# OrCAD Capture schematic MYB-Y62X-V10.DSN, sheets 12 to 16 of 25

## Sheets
12 PAGE10 - DUAL CHANNELS LVDS #: size A3; note: LVD1S & LVDS2
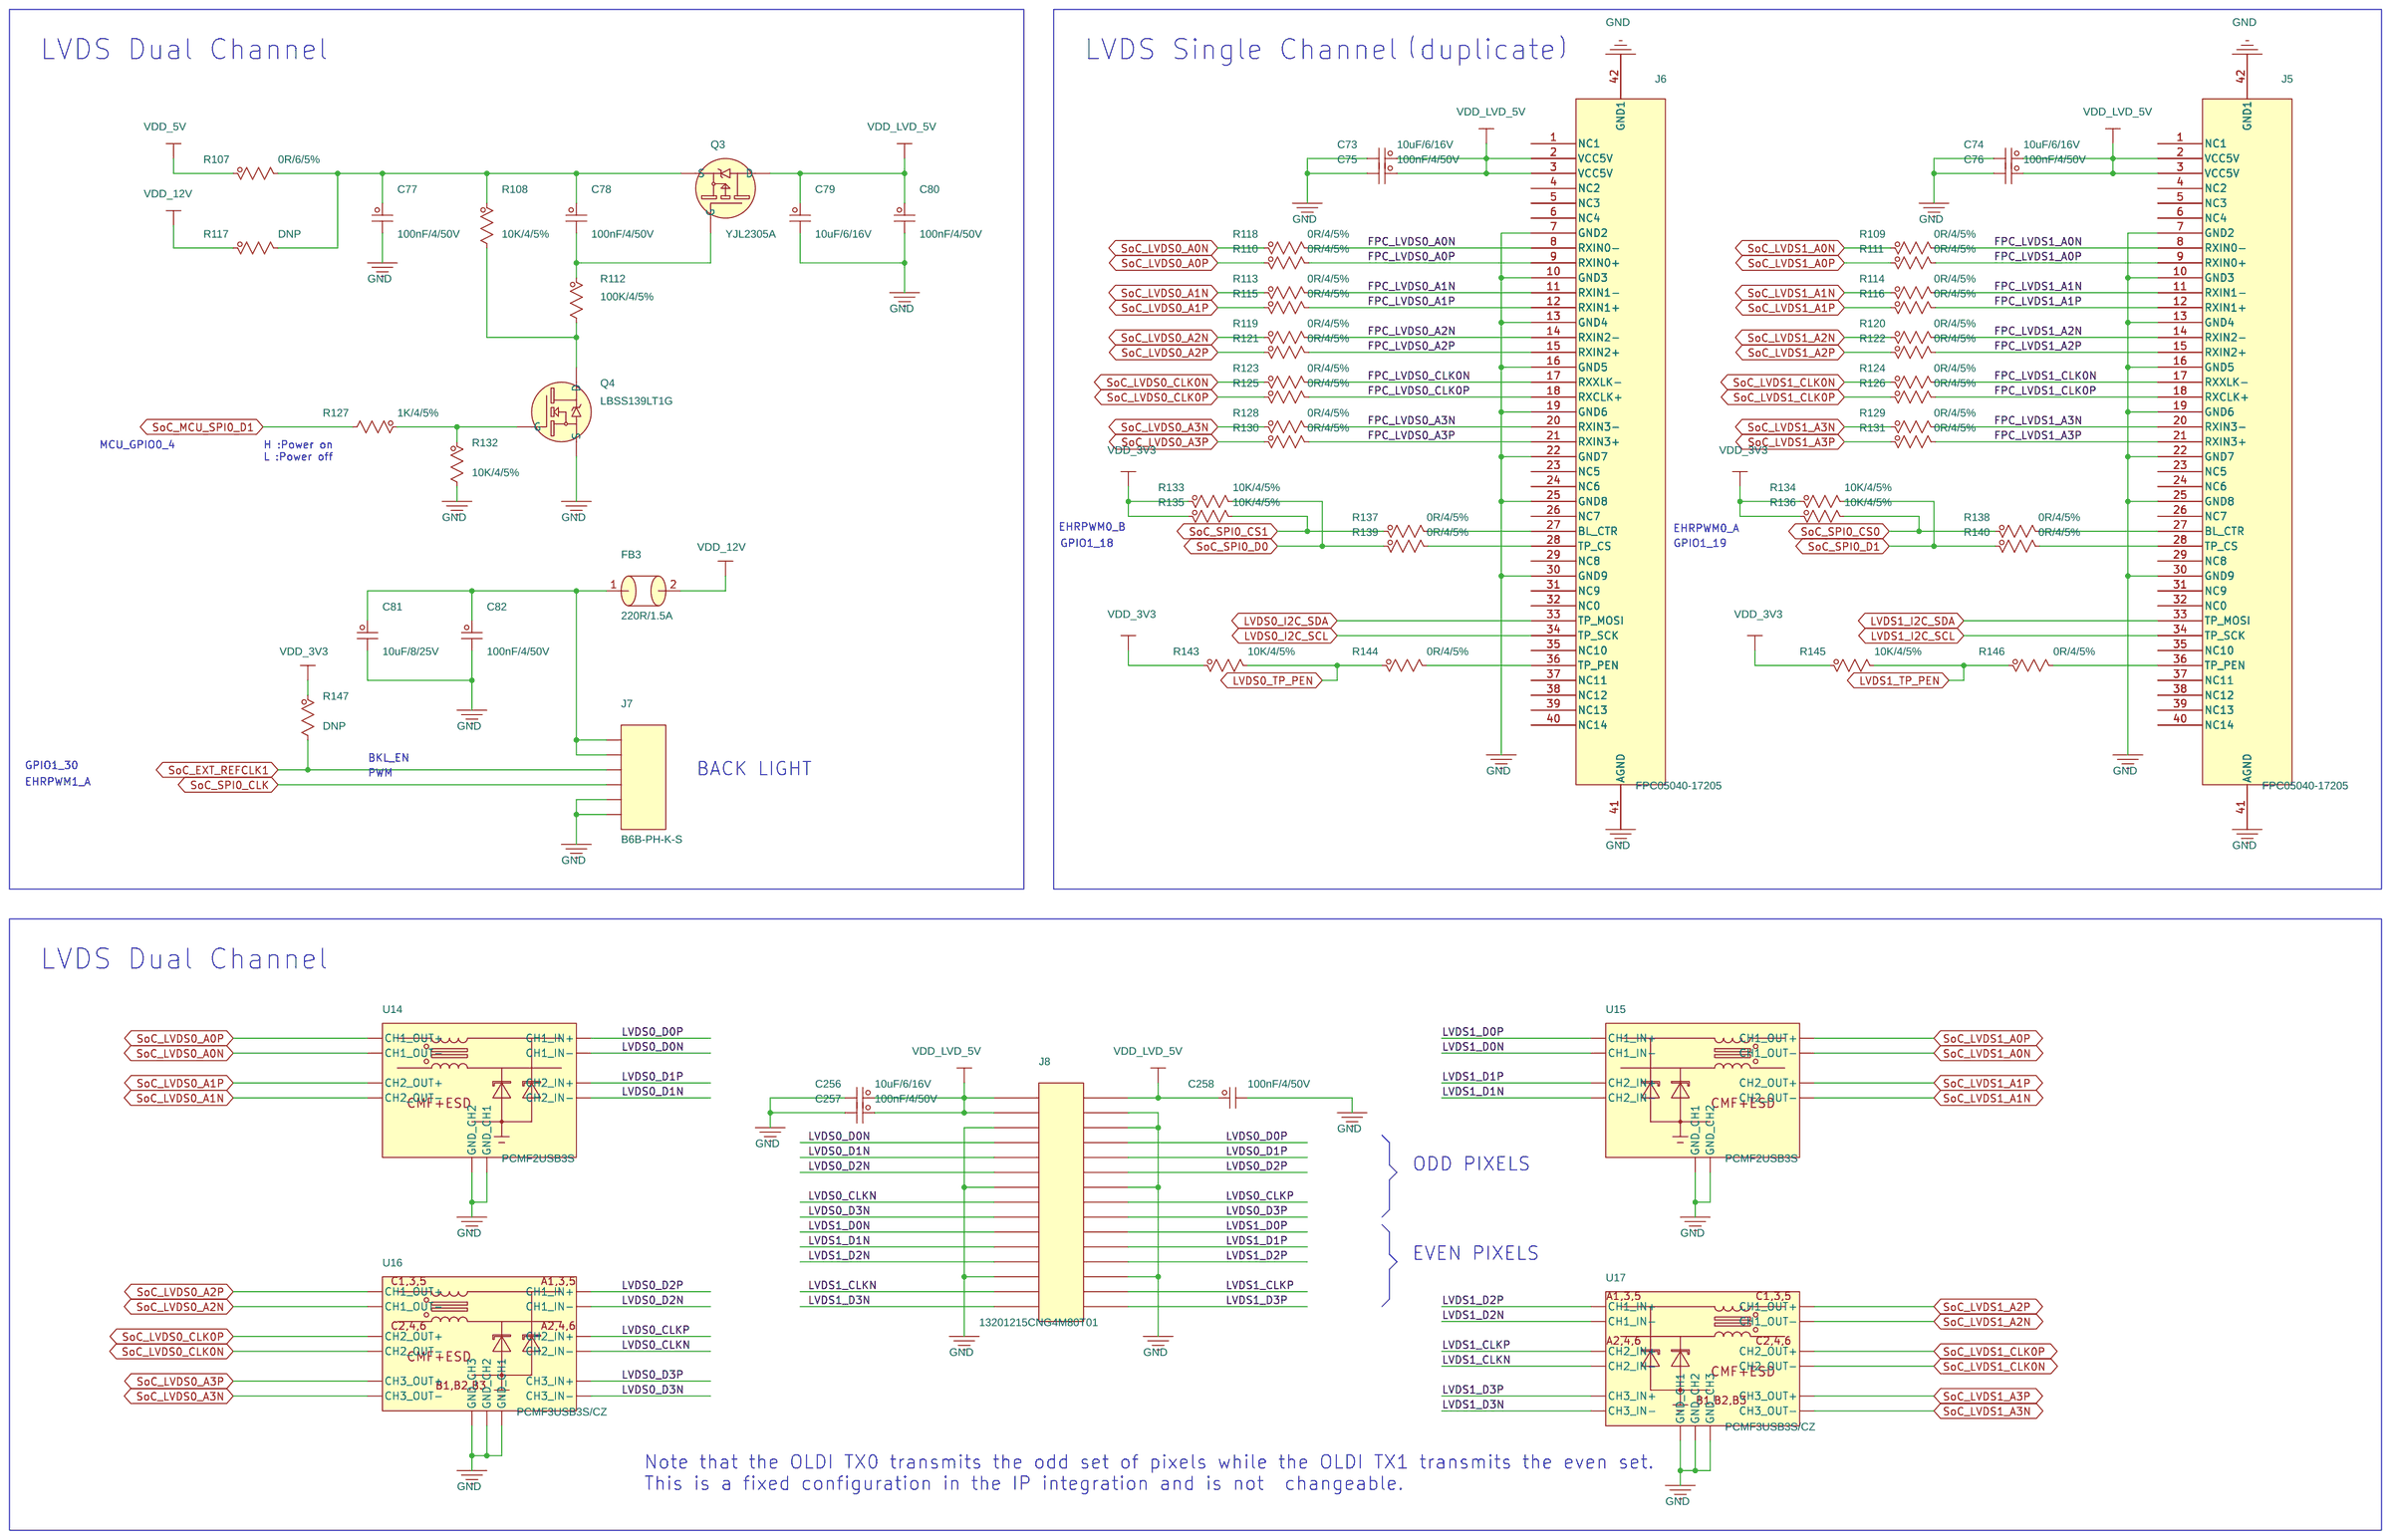
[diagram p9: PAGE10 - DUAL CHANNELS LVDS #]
13 PAGE11 - CSI - RX: size A3; note: CSI - RX
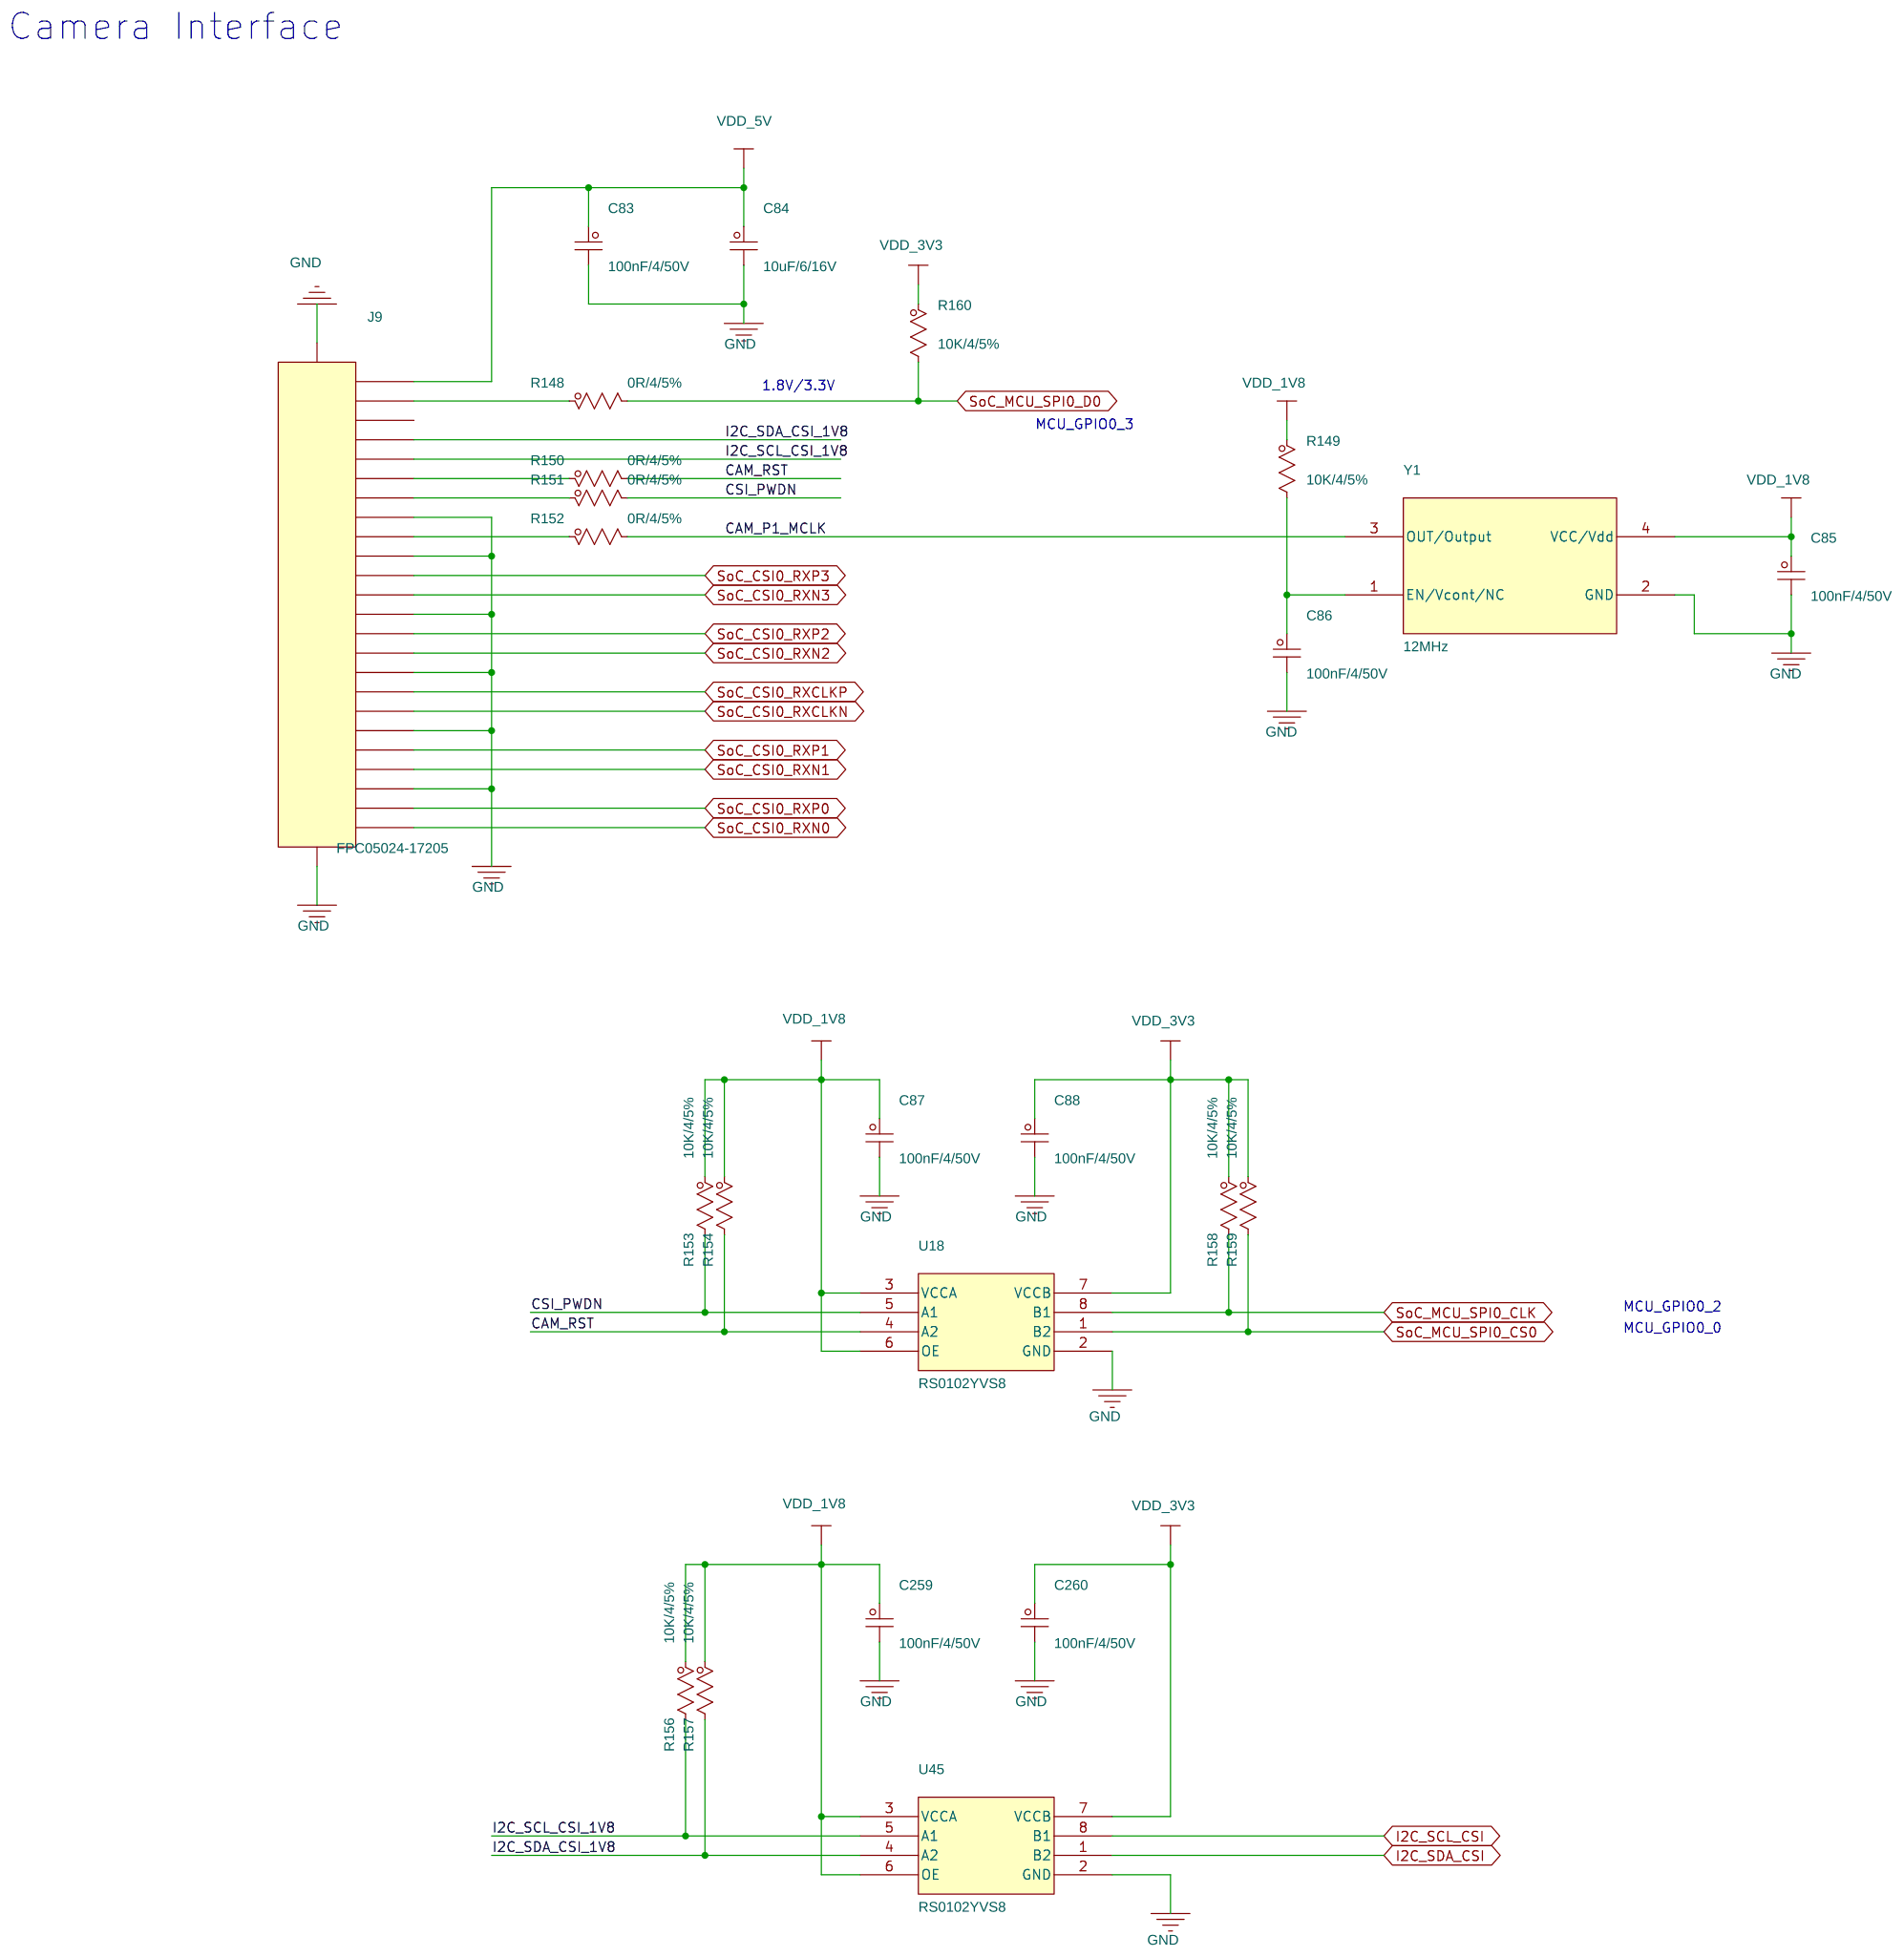
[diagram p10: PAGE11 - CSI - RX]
14 PAGE12 - HDMI & 8 BIT GPMC #: size C; note: DSS RGB
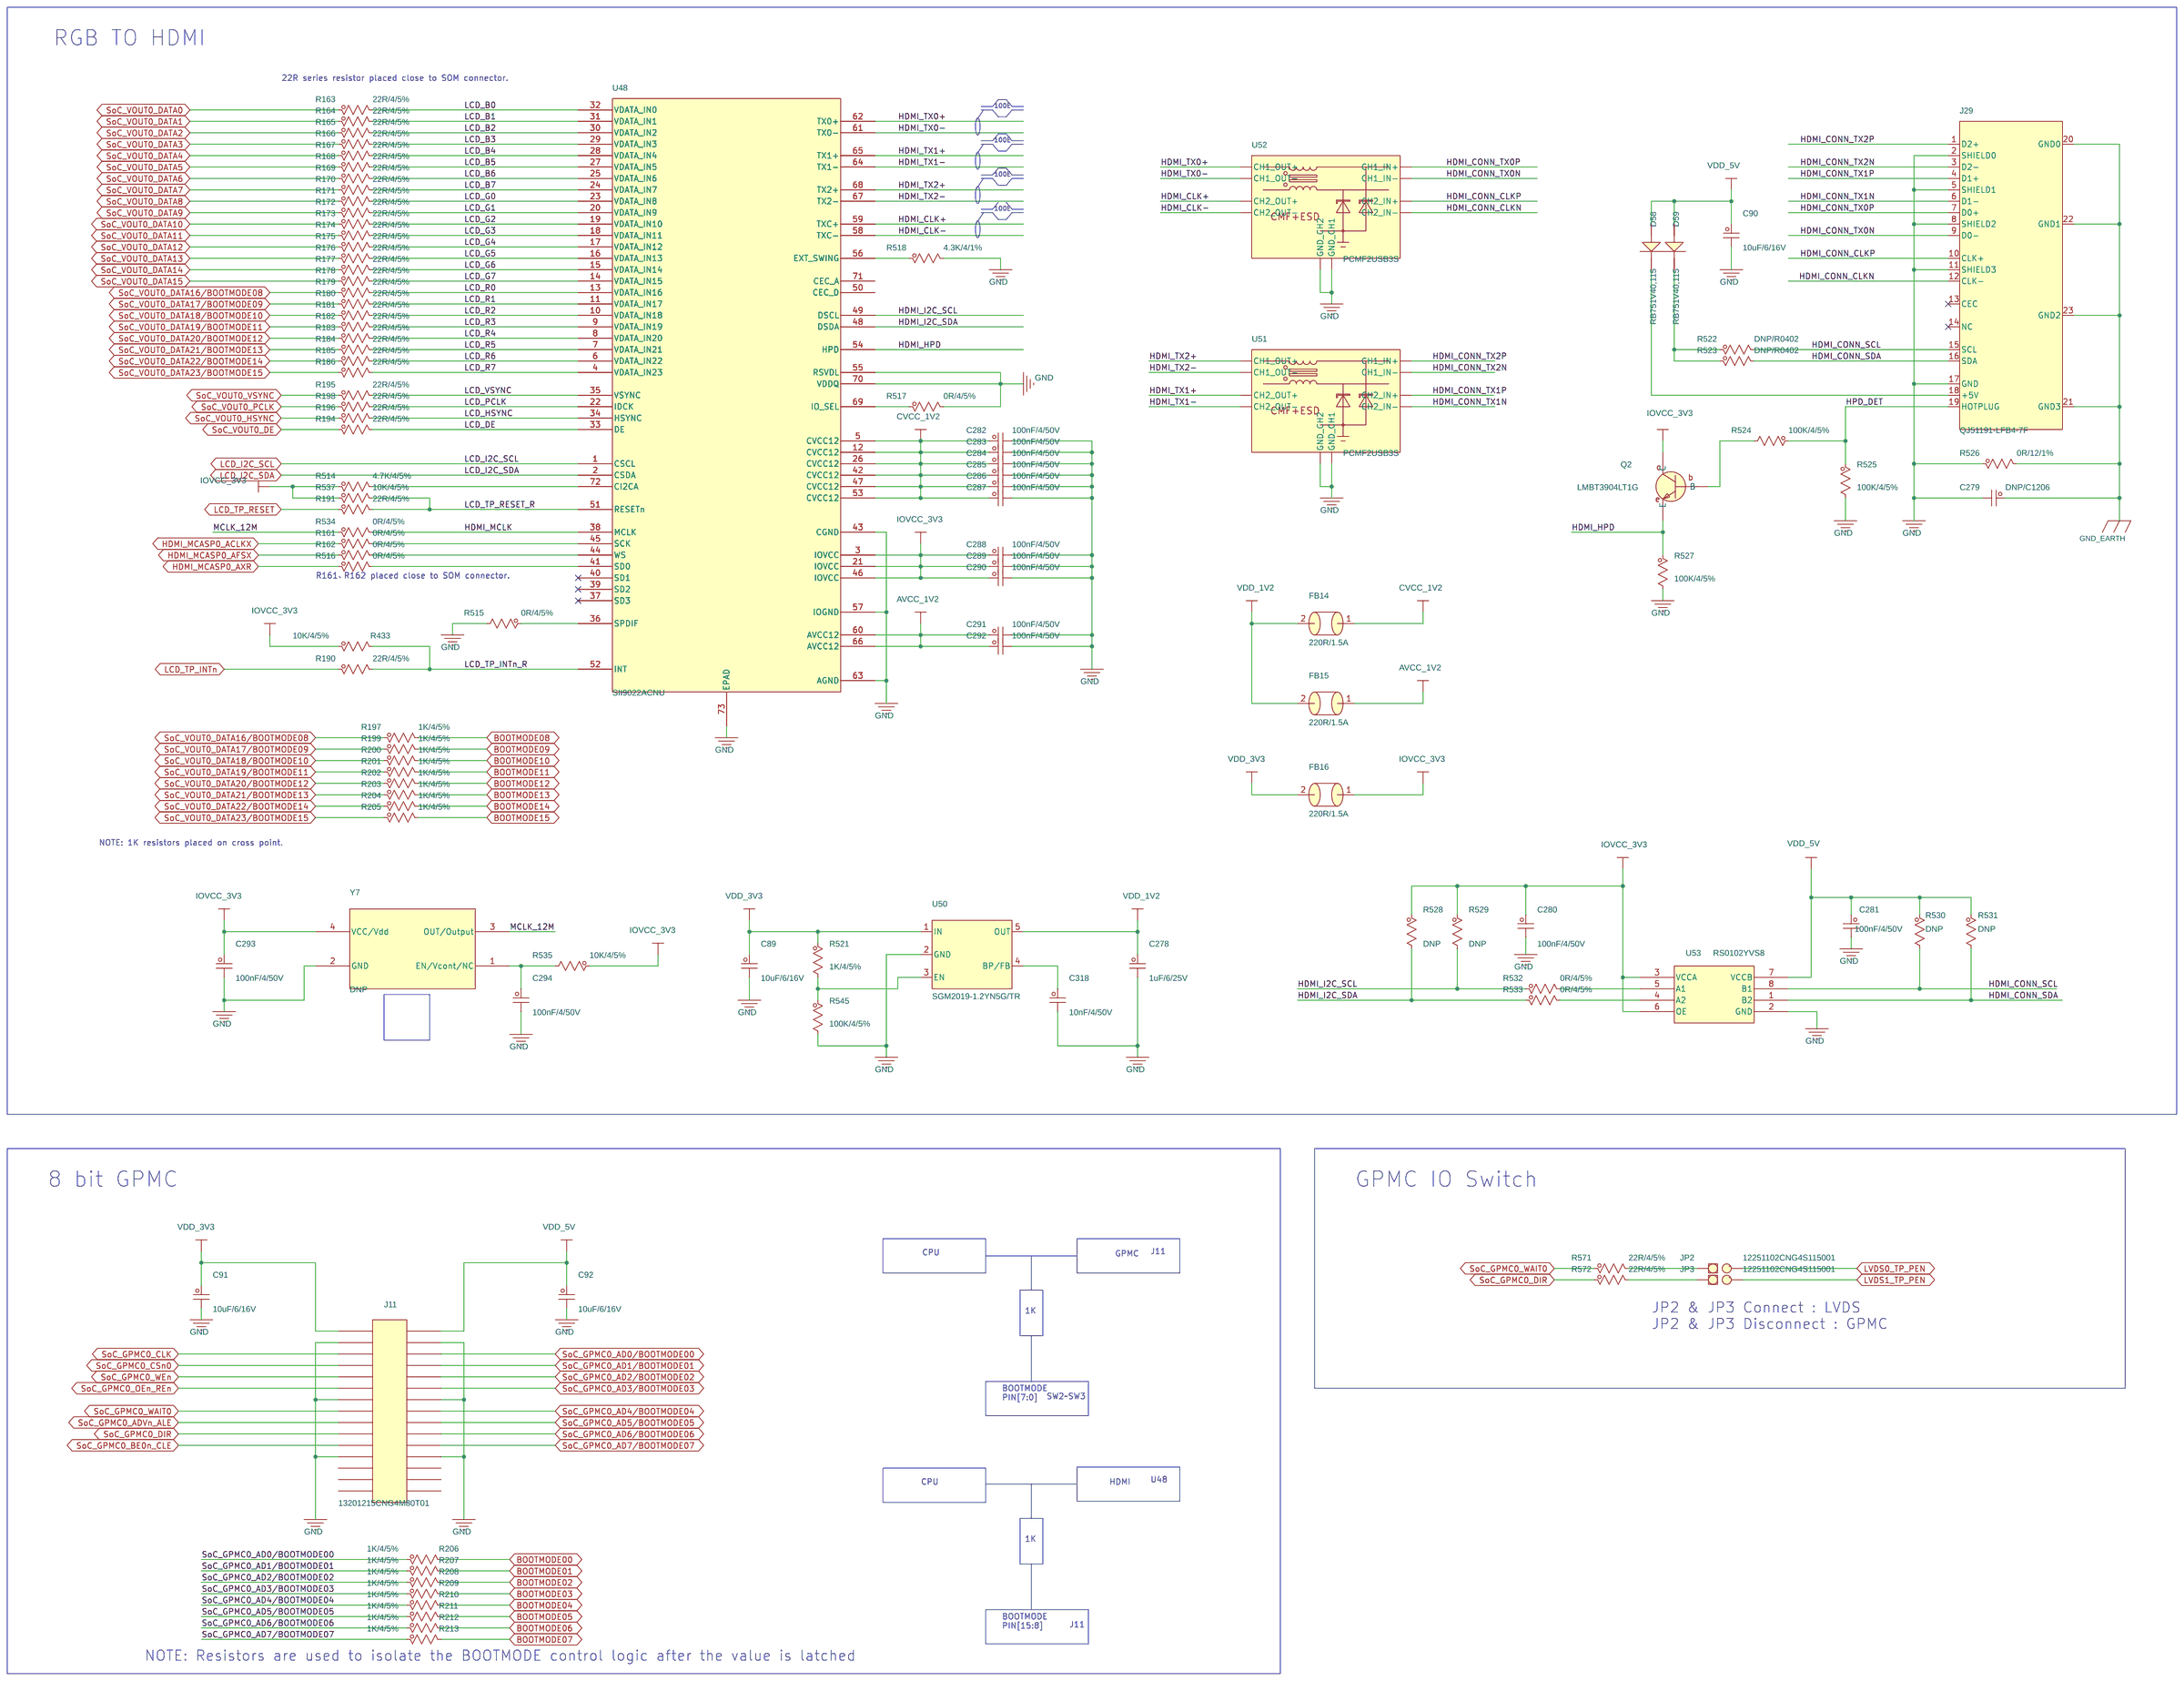
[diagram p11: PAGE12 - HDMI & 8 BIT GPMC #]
15 PAGE13 - BOOT MODE SWITCHES  #: size B; note: BOOT MODE SWITCHES
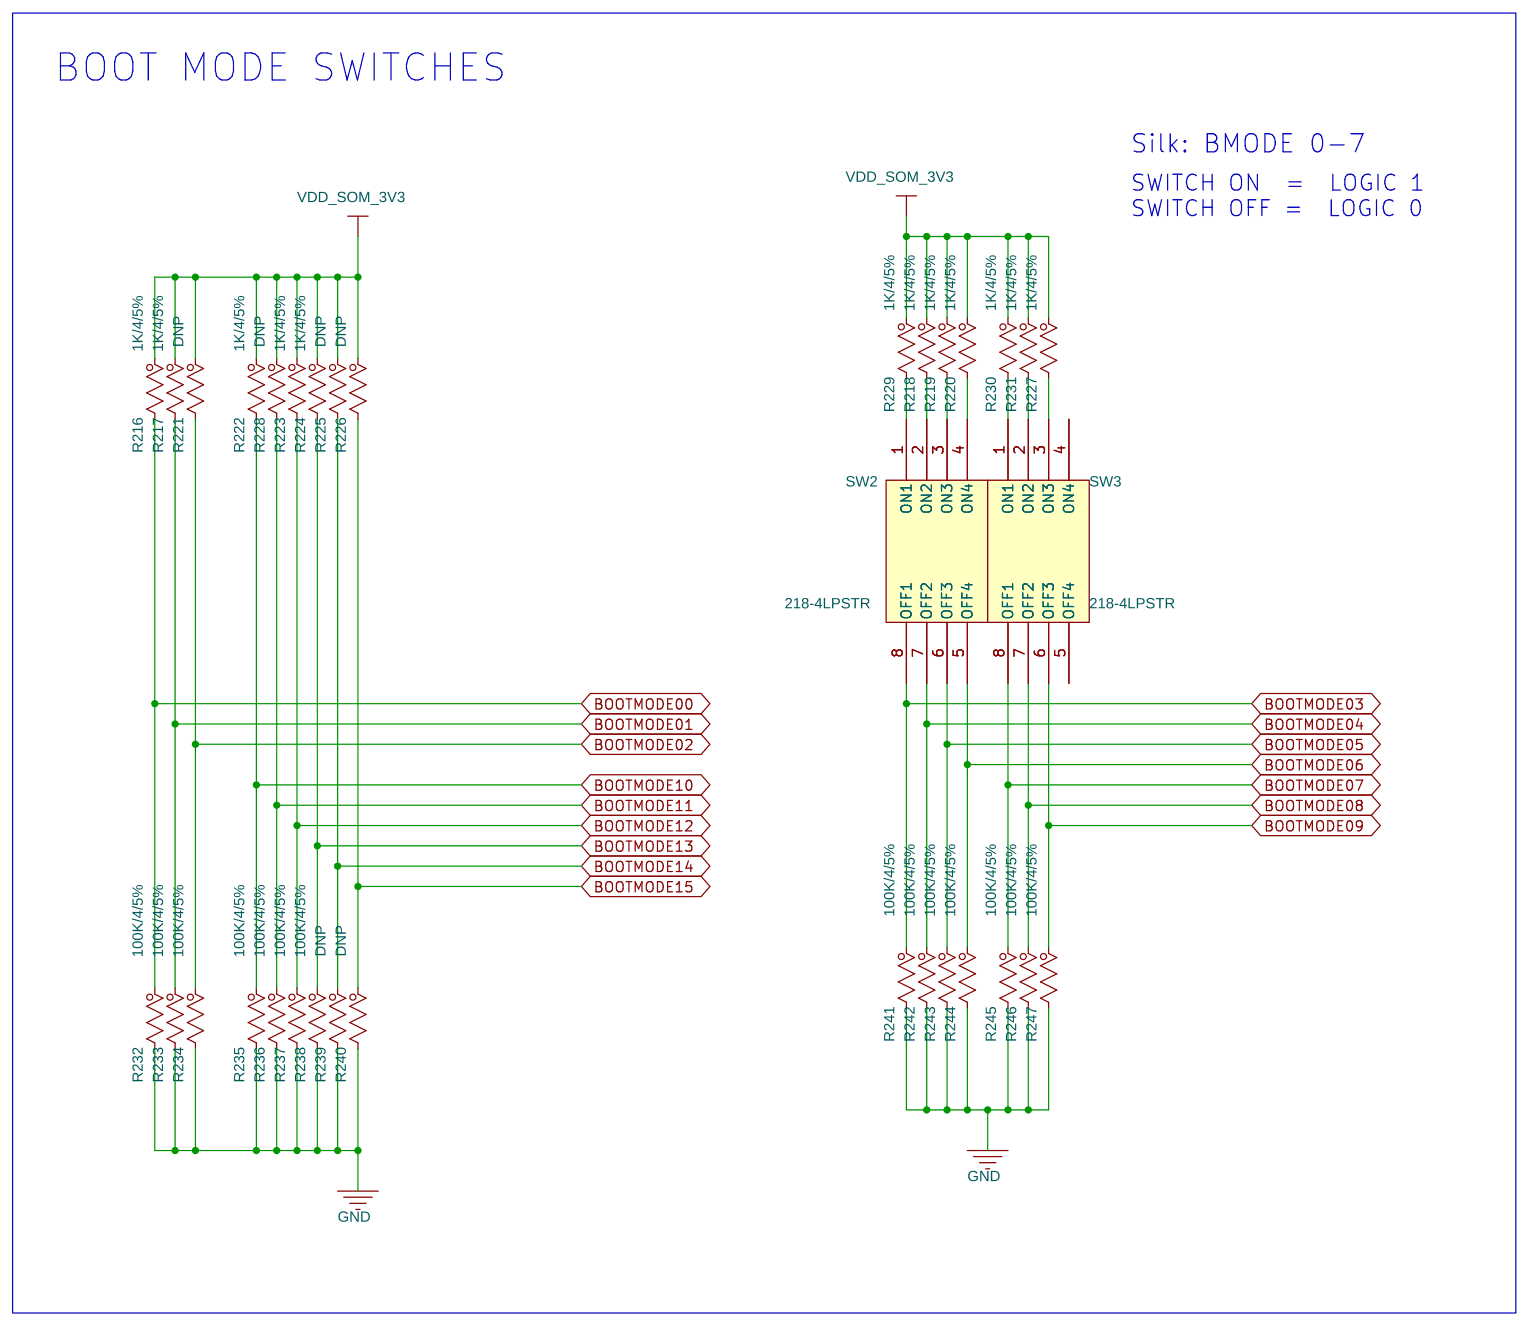
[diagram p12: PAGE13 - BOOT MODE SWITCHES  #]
16 PAGE17 - AUDIO CODEC #: size A3; note: AUDIO
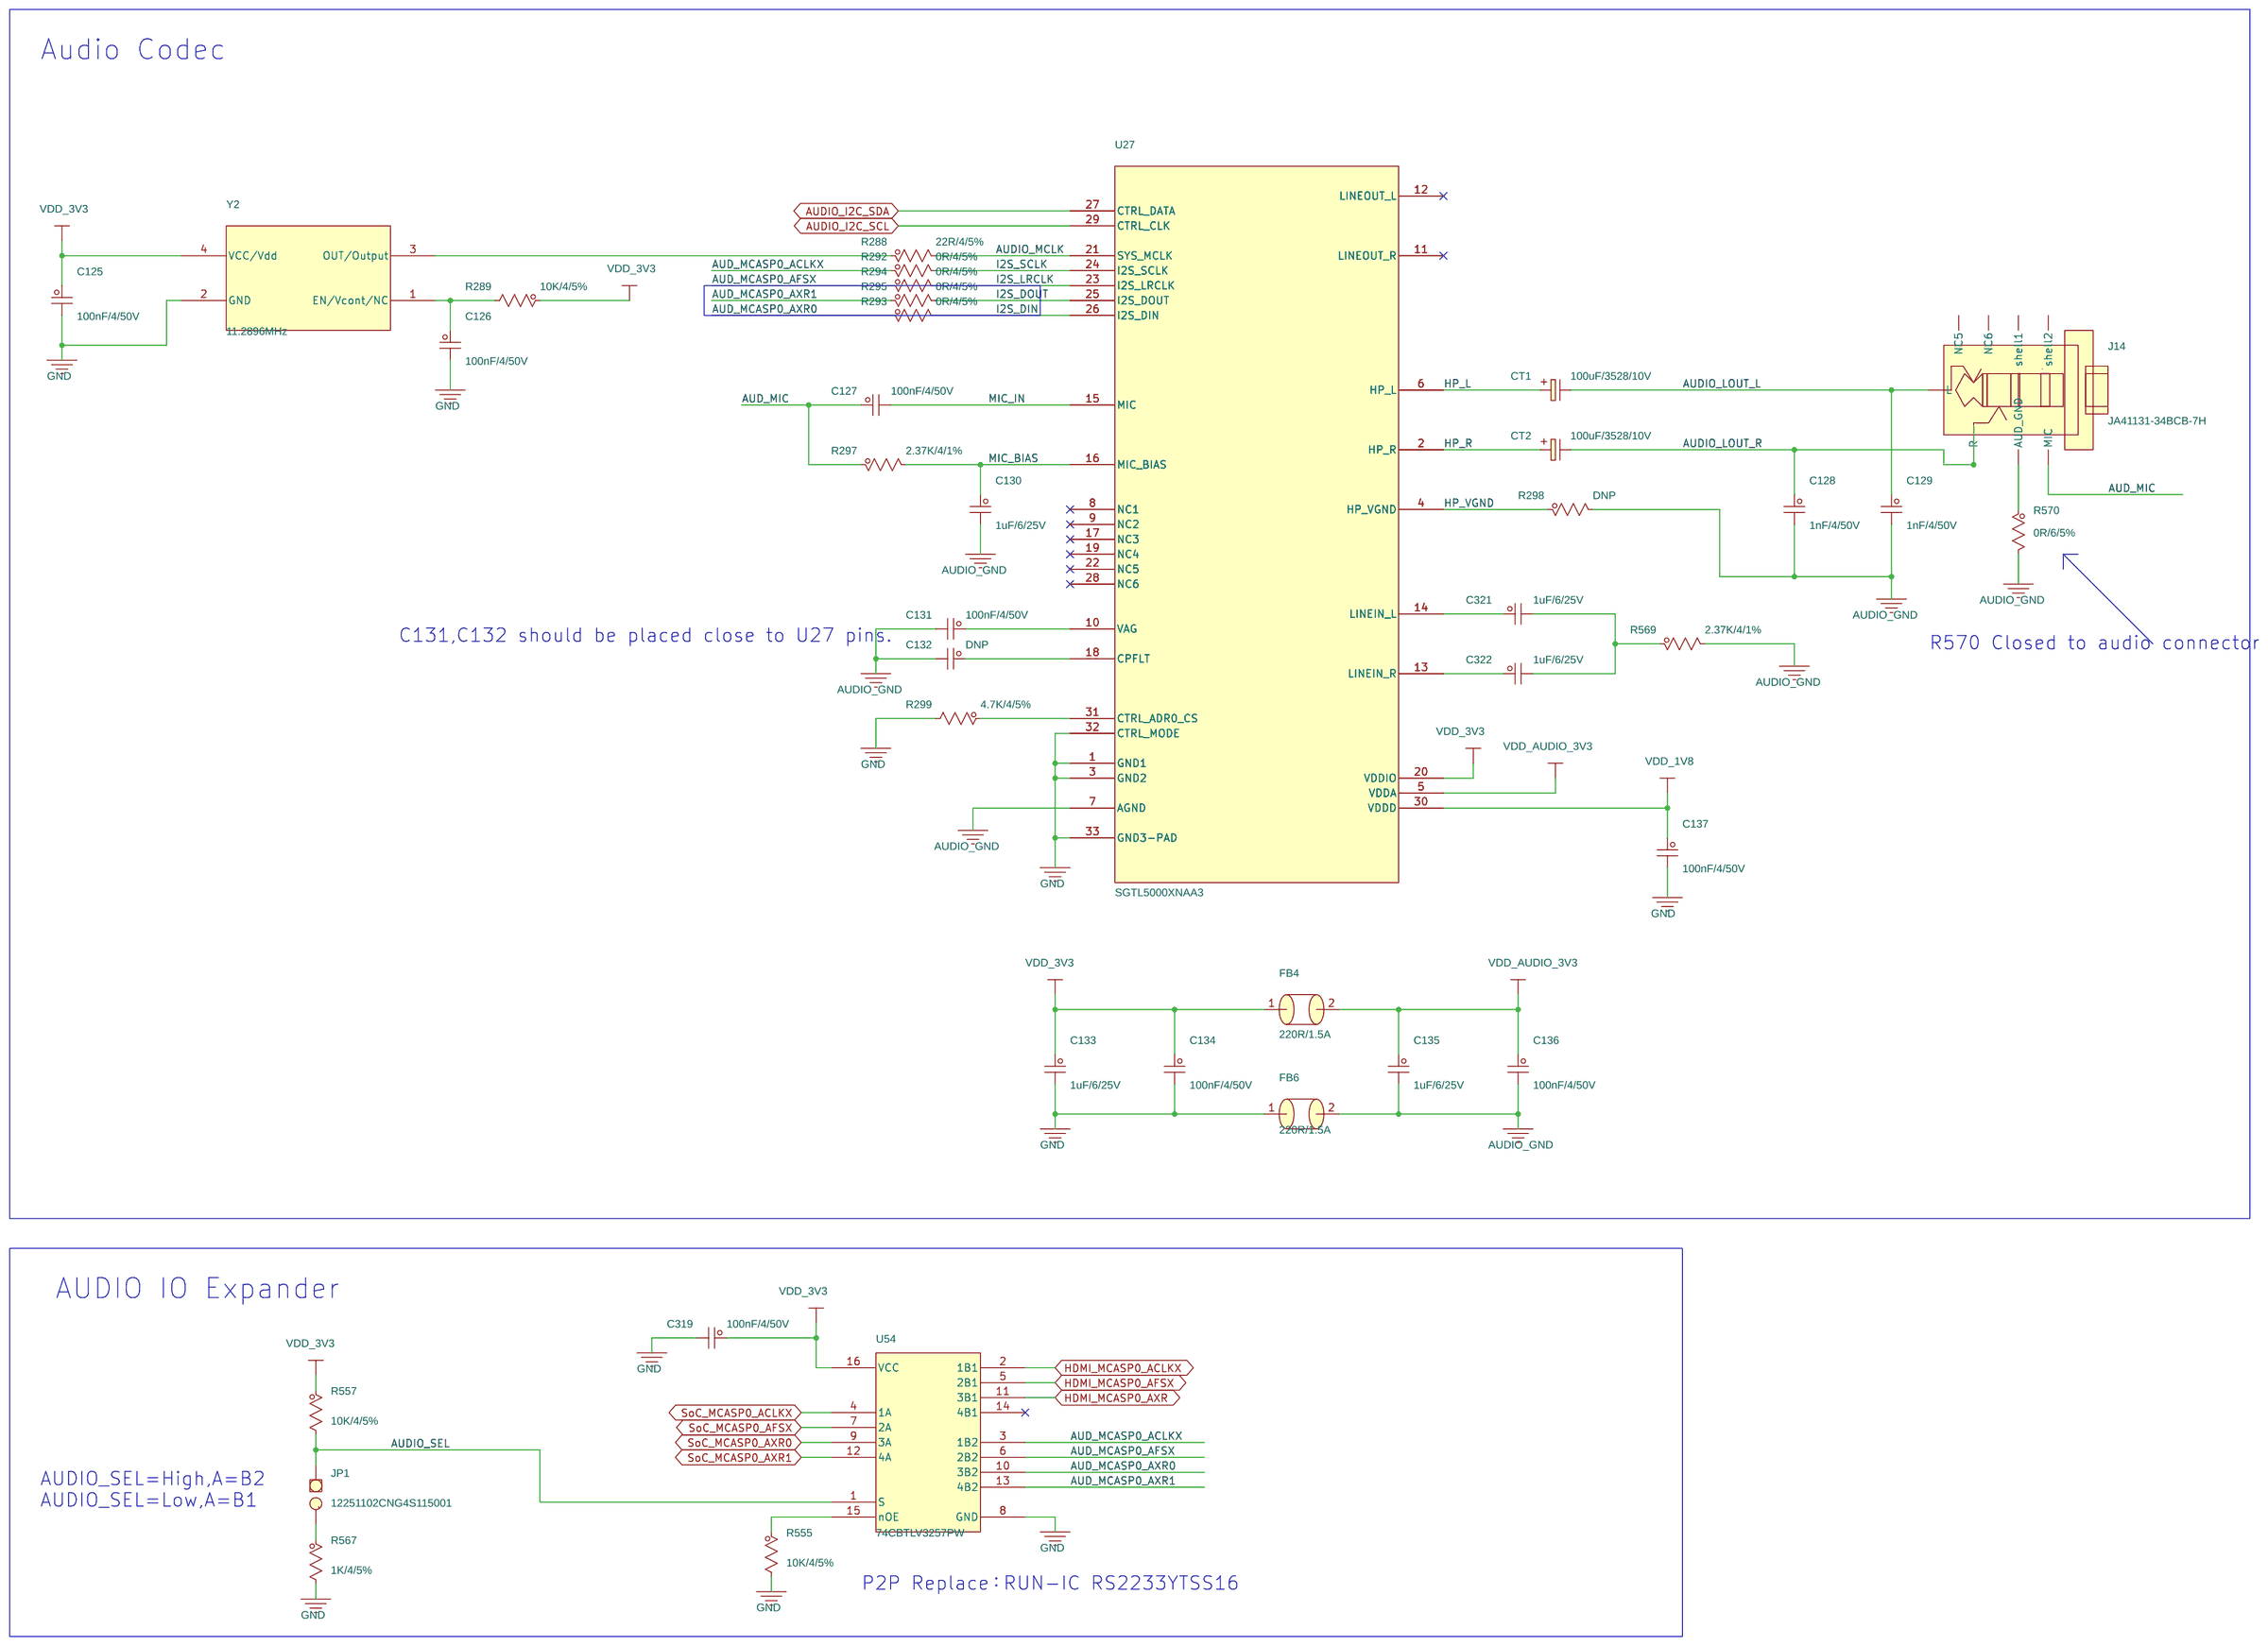
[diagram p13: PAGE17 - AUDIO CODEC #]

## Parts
sheet PAGE10 - DUAL CHANNELS LVDS #
C73  10uF/6/16V  [C0603]
C74  10uF/6/16V  [C0603]
C75  100nF/4/50V  [C0402]
C76  100nF/4/50V  [C0402]
C77  100nF/4/50V  [C0402]
C78  100nF/4/50V  [C0402]
C79  10uF/6/16V  [C0603]
C80  100nF/4/50V  [C0402]
C81  10uF/8/25V  [C0805]
C82  100nF/4/50V  [C0402]
C256  10uF/6/16V  [C0603]
C257  100nF/4/50V  [C0402]
C258  100nF/4/50V  [C0402]
FB3  220R/1.5A  [FB0603]
J5  FPC05040-17205  [FPC40-0_5-h]
J6  FPC05040-17205  [FPC40-0_5-h]
J7  B6B-PH-K-S  [CONN-B6B-PH-K]
J8  13201215CNG4M80T01  [CONN2x15-2_00-SMD]
Q3  YJL2305A  [SOT-23]
Q4  LBSS139LT1G  [SOT-23]
R107  0R/6/5%  [R0603]
R108  10K/4/5%  [R0402]
R109  0R/4/5%  [R0402]
R110  0R/4/5%  [R0402]
R111  0R/4/5%  [R0402]
R112  100K/4/5%  [R0402]
R113  0R/4/5%  [R0402]
R114  0R/4/5%  [R0402]
R115  0R/4/5%  [R0402]
R116  0R/4/5%  [R0402]
R117  DNP  [R0603]
R118  0R/4/5%  [R0402]
R119  0R/4/5%  [R0402]
R120  0R/4/5%  [R0402]
R121  0R/4/5%  [R0402]
R122  0R/4/5%  [R0402]
R123  0R/4/5%  [R0402]
R124  0R/4/5%  [R0402]
R125  0R/4/5%  [R0402]
R126  0R/4/5%  [R0402]
R127  1K/4/5%  [R0402]
R128  0R/4/5%  [R0402]
R129  0R/4/5%  [R0402]
R130  0R/4/5%  [R0402]
R131  0R/4/5%  [R0402]
R132  10K/4/5%  [R0402]
R133  10K/4/5%  [R0402]
R134  10K/4/5%  [R0402]
R135  10K/4/5%  [R0402]
R136  10K/4/5%  [R0402]
R137  0R/4/5%  [R0402]
R138  0R/4/5%  [R0402]
R139  0R/4/5%  [R0402]
R140  0R/4/5%  [R0402]
R143  10K/4/5%  [R0402]
R144  0R/4/5%  [R0402]
R145  10K/4/5%  [R0402]
R146  0R/4/5%  [R0402]
R147  DNP  [R0402]
U14  PCMF2USB3S  [WLCSP10]
U15  PCMF2USB3S  [WLCSP10]
U16  PCMF3USB3S/CZ  [WLCSP15]
U17  PCMF3USB3S/CZ  [WLCSP15]
sheet PAGE11 - CSI - RX
C83  100nF/4/50V  [C0402]
C84  10uF/6/16V  [C0603]
C85  100nF/4/50V  [C0402]
C86  100nF/4/50V  [C0402]
C87  100nF/4/50V  [C0402]
C88  100nF/4/50V  [C0402]
C259  100nF/4/50V  [C0402]
C260  100nF/4/50V  [C0402]
J9  FPC05024-17205  [FPC24-0_5-h]
R148  0R/4/5%  [R0402]
R149  10K/4/5%  [R0402]
R150  0R/4/5%  [R0402]
R151  0R/4/5%  [R0402]
R152  0R/4/5%  [R0402]
R153  10K/4/5%  [R0402]
R154  10K/4/5%  [R0402]
R156  10K/4/5%  [R0402]
R157  10K/4/5%  [R0402]
R158  10K/4/5%  [R0402]
R159  10K/4/5%  [R0402]
R160  10K/4/5%  [R0402]
U18  RS0102YVS8  [VSSOP8]
U45  RS0102YVS8  [VSSOP8]
Y1  12MHz  [3225]
sheet PAGE12 - HDMI & 8 BIT GPMC #
C89  10uF/6/16V  [C0603]
C90  10uF/6/16V  [C0603]
C91  10uF/6/16V  [C0603]
C92  10uF/6/16V  [C0603]
C278  1uF/6/25V  [C0603]
C279  DNP/C1206  [C1206]
C280  100nF/4/50V  [C0402]
C281  100nF/4/50V  [C0402]
C282  100nF/4/50V  [C0402]
C283  100nF/4/50V  [C0402]
C284  100nF/4/50V  [C0402]
C285  100nF/4/50V  [C0402]
C286  100nF/4/50V  [C0402]
C287  100nF/4/50V  [C0402]
C288  100nF/4/50V  [C0402]
C289  100nF/4/50V  [C0402]
C290  100nF/4/50V  [C0402]
C291  100nF/4/50V  [C0402]
C292  100nF/4/50V  [C0402]
C293  100nF/4/50V  [C0402]
C294  100nF/4/50V  [C0402]
C318  10nF/4/50V  [C0402]
D58  RB751V40,115  [SOD323]
D59  RB751V40,115  [SOD323]
FB14  220R/1.5A  [FB0603]
FB15  220R/1.5A  [FB0603]
FB16  220R/1.5A  [FB0603]
J11  13201215CNG4M80T01  [CONN2x15-2_00-SMD]
J29  QJ51191-LFB4-7F  [QJ51191-LFB4]
JP2  12251102CNG4S115001  [CONN1x2-2_54-dip]
JP3  12251102CNG4S115001  [CONN1x2-2_54-dip]
Q2  LMBT3904LT1G  [SOT-23]
R161  0R/4/5%  [R0402]
R162  0R/4/5%  [R0402]
R163  22R/4/5%  [R0402]
R164  22R/4/5%  [R0402]
R165  22R/4/5%  [R0402]
R166  22R/4/5%  [R0402]
R167  22R/4/5%  [R0402]
R168  22R/4/5%  [R0402]
R169  22R/4/5%  [R0402]
R170  22R/4/5%  [R0402]
R171  22R/4/5%  [R0402]
R172  22R/4/5%  [R0402]
R173  22R/4/5%  [R0402]
R174  22R/4/5%  [R0402]
R175  22R/4/5%  [R0402]
R176  22R/4/5%  [R0402]
R177  22R/4/5%  [R0402]
R178  22R/4/5%  [R0402]
R179  22R/4/5%  [R0402]
R180  22R/4/5%  [R0402]
R181  22R/4/5%  [R0402]
R182  22R/4/5%  [R0402]
R183  22R/4/5%  [R0402]
R184  22R/4/5%  [R0402]
R185  22R/4/5%  [R0402]
R186  22R/4/5%  [R0402]
R190  22R/4/5%  [R0402]
R191  22R/4/5%  [R0402]
R194  22R/4/5%  [R0402]
R195  22R/4/5%  [R0402]
R196  22R/4/5%  [R0402]
R197  1K/4/5%  [R0402]
R198  22R/4/5%  [R0402]
R199  1K/4/5%  [R0402]
R200  1K/4/5%  [R0402]
R201  1K/4/5%  [R0402]
R202  1K/4/5%  [R0402]
R203  1K/4/5%  [R0402]
R204  1K/4/5%  [R0402]
R205  1K/4/5%  [R0402]
R206  1K/4/5%  [R0402]
R207  1K/4/5%  [R0402]
R208  1K/4/5%  [R0402]
R209  1K/4/5%  [R0402]
R210  1K/4/5%  [R0402]
R211  1K/4/5%  [R0402]
R212  1K/4/5%  [R0402]
R213  1K/4/5%  [R0402]
R433  10K/4/5%  [R0402]
R514  4.7K/4/5%  [R0402]
R515  0R/4/5%  [R0402]
R516  0R/4/5%  [R0402]
R517  0R/4/5%  [R0402]
R518  4.3K/4/1%  [R0402]
R521  1K/4/5%  [R0402]
R522  DNP/R0402  [R0402]
R523  DNP/R0402  [R0402]
R524  100K/4/5%  [R0402]
R525  100K/4/5%  [R0402]
R526  0R/12/1%  [R1206]
R527  100K/4/5%  [R0402]
R528  DNP  [R0402]
R529  DNP  [R0402]
R530  DNP  [R0402]
R531  DNP  [R0402]
R532  0R/4/5%  [R0402]
R533  0R/4/5%  [R0402]
R534  0R/4/5%  [R0402]
R535  10K/4/5%  [R0402]
R537  10K/4/5%  [R0402]
R545  100K/4/5%  [R0402]
R571  22R/4/5%  [R0402]
R572  22R/4/5%  [R0402]
U48  SII9022ACNU  [QFN72]
U50  SGM2019-1.2YN5G/TR  [SOT23-5]
U51  PCMF2USB3S  [WLCSP10]
U52  PCMF2USB3S  [WLCSP10]
U53  RS0102YVS8  [VSSOP8]
Y7  DNP  [3225]
sheet PAGE13 - BOOT MODE SWITCHES  #
R216  1K/4/5%  [R0402]
R217  1K/4/5%  [R0402]
R218  1K/4/5%  [R0402]
R219  1K/4/5%  [R0402]
R220  1K/4/5%  [R0402]
R221  DNP  [R0402]
R222  1K/4/5%  [R0402]
R223  1K/4/5%  [R0402]
R224  1K/4/5%  [R0402]
R225  DNP  [R0402]
R226  DNP  [R0402]
R227  1K/4/5%  [R0402]
R228  DNP  [R0402]
R229  1K/4/5%  [R0402]
R230  1K/4/5%  [R0402]
R231  1K/4/5%  [R0402]
R232  100K/4/5%  [R0402]
R233  100K/4/5%  [R0402]
R234  100K/4/5%  [R0402]
R235  100K/4/5%  [R0402]
R236  100K/4/5%  [R0402]
R237  100K/4/5%  [R0402]
R238  100K/4/5%  [R0402]
R239  DNP  [R0402]
R240  DNP  [R0402]
R241  100K/4/5%  [R0402]
R242  100K/4/5%  [R0402]
R243  100K/4/5%  [R0402]
R244  100K/4/5%  [R0402]
R245  100K/4/5%  [R0402]
R246  100K/4/5%  [R0402]
R247  100K/4/5%  [R0402]
SW2  218-4LPSTR  [sw-2x4]
SW3  218-4LPSTR  [sw-2x4]
sheet PAGE17 - AUDIO CODEC #
C125  100nF/4/50V  [C0402]
C126  100nF/4/50V  [C0402]
C127  100nF/4/50V  [C0402]
C128  1nF/4/50V  [C0402]
C129  1nF/4/50V  [C0402]
C130  1uF/6/25V  [C0603]
C131  100nF/4/50V  [C0402]
C132  DNP  [C0603]
C133  1uF/6/25V  [C0603]
C134  100nF/4/50V  [C0402]
C135  1uF/6/25V  [C0603]
C136  100nF/4/50V  [C0402]
C137  100nF/4/50V  [C0402]
C319  100nF/4/50V  [C0402]
C321  1uF/6/25V  [C0603]
C322  1uF/6/25V  [C0603]
CT1  100uF/3528/10V  [CT3528-B]
CT2  100uF/3528/10V  [CT3528-B]
FB4  220R/1.5A  [FB0603]
FB6  220R/1.5A  [FB0603]
J14  JA41131-34BCB-7H  [AUDIO-JA41131-34BCB-7H]
JP1  12251102CNG4S115001  [CONN1x2-2_54-dip]
R288  22R/4/5%  [R0402]
R289  10K/4/5%  [R0402]
R292  0R/4/5%  [R0402]
R293  0R/4/5%  [R0402]
R294  0R/4/5%  [R0402]
R295  0R/4/5%  [R0402]
R297  2.37K/4/1%  [R0402]
R298  DNP  [R0402]
R299  4.7K/4/5%  [R0402]
R555  10K/4/5%  [R0402]
R557  10K/4/5%  [R0402]
R567  1K/4/5%  [R0402]
R569  2.37K/4/1%  [R0402]
R570  0R/6/5%  [R0603]
U27  SGTL5000XNAA3  [QFN32]
U54  74CBTLV3257PW  [TSSOP16]
Y2  11.2896MHz  [3225]

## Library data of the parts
C73 C74 C79 C84 C89-C92 C256 = Ceramic_Capacitor: Ceramic Capacitor,10uF,16V,+/-20%,X5R,0603,Samsung; Manufacturer: Samsung; Manufacturer P/N: CL10A106MO8NQNC; Myir P/N: 20401.80062; Part Type: Ceramic Capacitor; Reserve Value: 10uF; Datasheet: Samsung.pdf
C75-C78 C80 C82 C83 C85-C88 C125-C127 C131 C134 C136 C137 C257-C260 C280-C294 C319 = Ceramic_Capacitor: Ceramic Capacitor,100nF,50V,+/-10%,X7R,0402,Fenghua; Manufacturer: Fenghua; Manufacturer P/N: 0402B104K500NT; Myir P/N: 20401.80111; Part Type: Ceramic Capacitor; Reserve Value: 100nF; Datasheet: FENGHUA-Capacitor.pdf
C81 = Ceramic_Capacitor: Ceramic Capacitor, 10uF,25V,+/-10%,X5R,0805,Samsung; Manufacturer: Samsung; Manufacturer P/N: CL21A106KAYNNNE; Myir P/N: 20401.80094; Part Type: Ceramic Capacitor; Reserve Value: 10uF; Datasheet: Samsung.pdf
FB3 FB4 FB6 FB14-FB16 = Ferrite_Bead: Ferrite Bead,220R@100Mhz,1.5A,+/-25%,SMD,0603,Fenghua; Manufacturer: Fenghua; Manufacturer P/N: CBM160808U221T; Myir P/N: 20601.80007; Part Type: Ferrite Bead; Reserve Value: 220R; Datasheet: CBM160808U221T.pdf
J5 J6 = FPC40: FPC Connector,40pin,0.5mm pitch,Dual-sided Contact Models, Operating temperature range from–45~85℃,Atom; Manufacturer: Atom; Myir P/N: 21106.00016; Part Type: FPC Connector; Datasheet: FPC_Atom.pdf
J7 = B6B-PH-K-S: Connector,Straight,Top type 6Pin 2.0mm Pitch H=6mm,DIP,JST; Manufacturer: JST; Myir P/N: 21122.00013; Part Type: Other Connector; Datasheet: B6B-PH-K-S.pdf
J8 J11 = 2X15PIN: Connector,Pin Header,Straight,Male,2x15Pin,2.00mm pitch,PA=3.8,PB=2.5,L= 8.0,Gold Flash 4u, black,SMD,GDZ; Manufacturer: GDZ; Myir P/N: 21101.00045; Part Type: Connector; Datasheet: 13201215CNG3M110T01 2.0.pdf
Q3 = P-MOSFET: Mosfet,P-Channel,15V,70OHM,5.6A,SOT23,SMD,YangJie; Manufacturer: YangJie; Myir P/N: 20703.80039; Part Type: Mosfet; RP1 Manufacturer P/N: IRLML6401TRPBF; RP1 Myir P/N: 20703.00005; RP2 Manufacturer P/N: PMV48XPA; RP2 Myir P/N: 20703.00014; Datasheet: YJL2305A.pdf
Q4 = N-MOSFET: Mosfet,N-Channel,50V,0.2A,SMD,SOT-23,LRC; Manufacturer: LRC; Myir P/N: 20703.00012; Part Type: Mosfet; Datasheet: LBSS139LT1G.pdf
R107 R117 = Resister: Thick Film Resistor,0R,+/-5%,1/10W,-55°C ~ 155°C,SMD,0603,Fenghua; Manufacturer: Fenghua; Manufacturer P/N: RS-03000JT; Myir P/N: 20301.00214; Part Type: Thick Film Resistor; Reserve Value: 0R; Datasheet: FHsheet_2018-07-30.PDF
R108 R132-R136 R143 R145 R149 R153 R154 R156-R160 R289 R433 R535 R537 R555 R557 = Resister: Thick Film Resistor,10K,+/-5%,1/16W,-55°C ~ 155°C,SMD,0402,Fenghua; Manufacturer: Fenghua; Manufacturer P/N: RC-02W103JT; Myir P/N: 20301.00199; Part Type: Thick Film Resistor; Reserve Value: 10K; Datasheet: FHsheet_2018-07-30.PDF
R109-R111 R113-R116 R118-R126 R128-R131 R137-R140 R144 R146 R148 R150-R152 R161 R162 R292-R295 R298 R515-R517 R534 = Resister: Thick Film Resistor,0R,+/-5%,1/16W,-55°C ~ 155°C,SMD,0402,Fenghua; Manufacturer: Fenghua; Manufacturer P/N: RC-02000JT; Myir P/N: 20301.00186; Part Type: Thick Film Resistor; Reserve Value: 0R; Datasheet: FHsheet_2018-07-30.PDF
R112 R232-R247 R545 = Resister: Thick Film Resistor,100K,+/-5%,,1/16W,-55°C ~ 155°C,SMD,0402,Fenghua; Manufacturer: Fenghua; Manufacturer P/N: RC-02W104JT; Myir P/N: 20301.00210; Part Type: Thick Film Resistor; Reserve Value: 100K; Datasheet: FHsheet_2018-07-30.PDF
R127 R197 R199-R213 R216-R231 R521 = Resister: Thick Film Resistor,1K,+/-5%,1/16W,-55°C ~ 155°C,SMD,0402,Fenghua; Manufacturer: Fenghua; Manufacturer P/N: RC-02W102JT; Myir P/N: 20301.80389; Part Type: Thick Film Resistor; Reserve Value: 1K; Datasheet: FHsheet_2018-07-30.PDF
R147 = Resister: Thick Film Resistor,10K,+/-1%,1/16W,SMD,0402,Yageo; Manufacturer: Yageo; Manufacturer P/N: RC0402FR-0710KL; Myir P/N: 2030100036; Part Type: Thick Film Resistor; Reserve Value: 10K; Datasheet: 0402_Thick Film Resistor.pdf
U14 U15 U51 U52 = PCMF2USB3S: IC,Common-mode EMI filter for 2 channels with integrated ESD protection,SMD,WLCSP10,PF2S,NXP; Manufacturer: NXP; Myir P/N: 20114.00011; Part Type: Protection; Datasheet: PCMFxUSB3S.pdf
U16 U17 = PCMF3USB3S: IC,Common-mode EMI filter for 3 channels with integrated ESD protection,SMD,WLCSP15,PF3S,NXP; Manufacturer: NXP; Myir P/N: 20114.00010; Part Type: Protection; Datasheet: PCMFxUSB3S.pdf
J9 = FPC24: FPC Connector,24pin,0.5mm pitch,Dual-sided Contact Models, Operating temperature range from–45~85℃,Atom; Manufacturer: Atom; Myir P/N: 21106.00017; Part Type: FPC Connector; Datasheet: FPC_Atom.pdf
U18 U45 U53 = TXS0102DCT: IC,2-Bit Bidirectional Voltage-Level Translator for Open-Drain and Push-Pull Application,SMD,VSSOP8,Runic; Manufacturer: Runic; Myir P/N: 20105.00030; Part Type: Logic; Datasheet: RS0102.pdf
Y1 = Oscillator_4P: Oscillator, 12MHz, +/-50ppm,3.3V,3225,SMD,TaiTien; Manufacturer: TaiTien; Manufacturer P/N: OXKTGLJANF-12.000000MHz; Myir P/N: 20902.00009; Part Type: Oscillator; RP1 Manufacturer P/N: 7X12000007; RP1 Myir P/N: 20902.00004; Datasheet: OXKTGLJANF-12.000000MHz 3225 12MHz 1.8~3.3V 50ppm 4pin.pdf
C130 C133 C135 C278 C321 C322 = Ceramic_Capacitor: Ceramic Capacitor,1uF, 25V,+/-10%,X5R,0603,Samsung; Manufacturer: Samsung; Manufacturer P/N: CL10A105KA8NNNC; Myir P/N: 20401.80063; Part Type: Ceramic Capacitor; Reserve Value: 1uF; Datasheet: Samsung.pdf
C279 = Ceramic_Capacitor: DNP; Manufacturer: DNP; Manufacturer P/N: DNP; Myir P/N: DNP; Part Type: DNP; Reserve Value: DNP; Datasheet: DNP
C318 = Ceramic_Capacitor: Ceramic Capacitor,10nF,50V,+/-10%,X7R,0402,Fenghua; Manufacturer: Fenghua; Manufacturer P/N: 0402B103K500NT; Myir P/N: 20401.80103; Part Type: Ceramic Capacitor; Reserve Value: 10nF; Datasheet: FENGHUA-Capacitor.pdf
D58 D59 = General_Diode: Diode Schottky, 40V 0.12A,SMD  2-Pin SOD-323,W8,NXP; Manufacturer: NXP; Myir P/N: 20701.00009; Part Type: Diode; Datasheet: RB751_SER.pdf
J29 = HDMI: Connector,HDMI A port,x1,Right Angle,Female,Gold Flash 1u,black,SMD,Foxconn; Manufacturer: Foxconn; Myir P/N: 21108.00004; Part Type: Display Connector; Datasheet: QJ51191-LFB4-7F.pdf
JP1-JP3 = SIP2-DROIT: Connector,PH,Straight,Male,1x2Pin,2.54mm,Pitch,PA6.0,PC3.0,Gold Flash 3u,Black,DIP,GDZ; Manufacturer: GDZ; Myir P/N: 21101.00041; Part Type: Connector; RP1 Manufacturer P/N: 3131025311161; RP1 Myir P/N: 21101.00001; Datasheet: 12251102CNG4S115001 2.54 1x2P.pdf
Q2 = NPN_Transistor: BJT,NPN,40V,200mA,SMD,SOT-23,LRC; Manufacturer: LRC; Myir P/N: 20702.00005; Part Type: BJT; Datasheet: LMBT3904LT1G.pdf
R163-R186 R190 R191 R194-R196 R198 = Resister: Thick Film Resistor,22R,+/-5%,1/16W,-55°C ~ 155°C,SMD,0402,Fenghua; Manufacturer: Fenghua; Manufacturer P/N: RC-02W220JT; Myir P/N: 20301.00187; Part Type: Thick Film Resistor; Reserve Value: 22R; Datasheet: FHsheet_2018-07-30.PDF
R299 R514 = Resister: Thick Film Resistor,4.7K,+/-5%,1/16W,-55°C ~ 155°C,SMD,0402,Fenghua; Manufacturer: Fenghua; Manufacturer P/N: RC-02W472JT; Myir P/N: 20301.80393; Part Type: Thick Film Resistor; Reserve Value: 4.7K; Datasheet: FHsheet_2018-07-30.PDF
R518 = Resister: Thick Film Resistor,4.3K,+/-1%,1/16W,-55°C ~ 155°C,SMD,0402,Yageoua; Manufacturer: Fenghua; Manufacturer P/N: RC0402FR-074K3L; Myir P/N: 20301.00028; Part Type: Thick Film Resistor; Reserve Value: 0R; Datasheet: FHsheet_2018-07-30.PDF
R522 R523 = Resister: DNP; Manufacturer: DNP; Manufacturer P/N: DNP; Myir P/N: DNP; Part Type: DNP; Reserve Value: DNP; Datasheet: DNP
R524 R525 R527 = Resister: Thick Film Resistor,100K,+/-5%,,1/16W,-55°C ~ 155°C,SMD,0402,Fenghua; Manufacturer: Fenghua; Manufacturer P/N: RC-02W104JT; Myir P/N: 20301.00210; Part Type: Thick Film Resistor; Reserve Value: 100K; Datasheet: FH规格书_2018-07-30.pdf
R526 = Resister: Thick Film Resistor,0R,+/-1%,1/4W,-55℃~155℃,SMD,1206,Reel,Fenghua; Manufacturer: Fenghua; Manufacturer P/N: RS-06000FT; Myir P/N: 20301.00312; Part Type: Thick Film Resistor; Reserve Value: 0R; Datasheet: FHsheet-20230524.pdf
R528-R531 = RESISTER: Thick Film Resistor,2.2K,+/-5%,1/16W,-55°C ~ 155°C,SMD,0402,Fenghua; Manufacturer: Fenghua; Manufacturer P/N: RC-02W222JT; Myir P/N: 20301.00195; Part Type: Thick Film Resistor; Reserve Value: 2.2K; Datasheet: FH规格书_2018-07-30.pdf
R532 R533 = Resister: Thick Film Resistor,0R,+/-5%,1/16W,-55°C ~ 155°C,SMD,0402,Fenghua; Manufacturer: Fenghua; Manufacturer P/N: RC-02000JT; Myir P/N: 20301.00186; Part Type: Thick Film Resistor; Reserve Value: 0R; Datasheet: FH规格书_2018-07-30.pdf
R288 R571 R572 = Resister: Thick Film Resistor,22R,+/-5%,1/16W,-55℃~155℃,SMD,0402,Fenghua; Manufacturer: Fenghua; Manufacturer P/N: RC-02W220JT; Myir P/N: 20301.00187; Part Type: Thick Film Resistor; Reserve Value: 22R; Datasheet: FHsheet_2018-07-30.PDF
U48 = SII9022A: IC,RGB to HDMI Transmitter,-20°C ~ 85°C,SMD,QFN72,SII9022ACNU,Silicon; Manufacturer: Silicon; Myir P/N: 20107.00013; Part Type: Interface; Datasheet: SiI9022-24A.pdf
U50 = SGM2019: IC,LDO Regulator,500mA,Voltage Output 1.2V,SMD,SOT23-5,Sgmicro; Manufacturer: Sgmicro; Myir P/N: 20103.00084; Part Type: Power Management; RP1 Manufacturer P/N: RT9013-12GB; RP1 Myir P/N: 20103.00007; Datasheet: SGM2019.pdf
Y7 = Oscillator_4P: Oscillator,11.2896MHz,+/-20ppm,15pF,3.3V,4Pin,3225,-40℃ to +85℃,SMD,SJK; Manufacturer: SJK; Manufacturer P/N: SJK-3N11289M3C0420B8; Myir P/N: 20902.00016; Part Type: Oscillator; Reserve Value: 11.2896MHz; Datasheet: SJK-3N11289M3C0420B8.pdf
SW2 SW3 = SWITCH-4: Switch, Dip Switches SPST 4 switch sections,4 Position,1.27mm Pitch,black housing,white plunger,SMD,CTS; Manufacturer: CTS; Myir P/N: 21203.00002; Part Type: Switch; Datasheet: 218-786217.pdf
C128 C129 = Ceramic_Capacitor: Ceramic Capacitor,1nF,50V,+/-10%,X7R,0402,Fenghua; Manufacturer: Fenghua; Manufacturer P/N: 0402B102K500NT; Myir P/N: 20401.80096; Part Type: Ceramic Capacitor; Reserve Value: 1nF; Datasheet: FENGHUA-Capacitor.pdf
C132 = Ceramic_Capacitor: Ceramic Capacitor,100nF, 50V, +/-10%, X7R, 0603,Fenghua; Manufacturer: Fenghua; Manufacturer P/N: 0603B104K500NT; Myir P/N: 20401.80129; Part Type: Ceramic Capacitor; Reserve Value: 100nF; Datasheet: FENGHUA-Capacitor.pdf
CT1 CT2 = Tantalum_Capacitor: Tantalum Capacitor,100uF,+/-20%,10V,SMD,3528(B),AVX; Manufacturer: AVX; Manufacturer P/N: TAJB107M010RNJ; Myir P/N: 20403.00003; Part Type: Tantalum Capacitor; Reserve Value: 100uF; Datasheet: Tantalum Capacitor.pdf
J14 = JA41131-34BCB-7H: Connector,Φ3.50mm with 4 Pole with single audio jack,OP ranges from -25 to 70℃; Manufacturer: Foxconn; Myir P/N: 21116.00004; Part Type: Audio Connector; Datasheet: JA4113x-34BCB-7H_305-0000-6297_A.pdf
R297 R569 = Resister: Thick Film Resistor,2.37K,+/-1%,1/16W,-55°C ~ 155°C,SMD,0402,Fenghua; Manufacturer: Fenghua; Manufacturer P/N: RC-02W2371FT; Myir P/N: 20301.00196; Part Type: Thick Film Resistor; Reserve Value: 2.37K; Datasheet: FHsheet_2018-07-30.PDF
R567 = Resister: Thick Film Resistor,1K,+/-5%,1/16W,-55℃~155℃,SMD,0402,Fenghua; Manufacturer: Fenghua; Manufacturer P/N: RC-02W102JT; Myir P/N: 20301.80389; Part Type: Thick Film Resistor; Reserve Value: 1K; Datasheet: FHsheet_2018-07-30.PDF
R570 = Resister: Thick Film Resistor,0R,+/-5%,1/10W,-55℃~155℃,SMD,0603,Fenghua; Manufacturer: Fenghua; Manufacturer P/N: RS-03000JT; Myir P/N: 20301.00214; Part Type: Thick Film Resistor; Reserve Value: 0R; Datasheet: FHsheet_2018-07-30.PDF
U27 = SGTL5000: IC,Low Power Stereo Codec with Headphone Amp,SMD,QFN32,NXP; Manufacturer: NXP; Myir P/N: 20107.00029; Part Type: Interface; Datasheet: SGTL5000.pdf
U54 = SN74CBTLV3257: IC,1-of-2 high-speed multiplexer/demultiplexer,SMD,TSSOP16,CL257,Nexpetia; Manufacturer: Nexpetia; Myir P/N: 20105.00028; Part Type: Logic; RP1 Manufacturer P/N: SN74CBTLV3257PWR; RP1 Myir P/N: 20105.00006; Datasheet: 74CBTLV3257.pdf
Y2 = Oscillator_4P: Oscillator,11.2896MHz,+/-20ppm,15pF,3.3V,4Pin,3225,-40℃ to +85℃,SMD,SJK; Manufacturer: SJK; Manufacturer P/N: SJK-3N11289M3C0420B8; Myir P/N: 20902.00016; Part Type: Oscillator; Datasheet: SJK-3N11289M3C0420B8.pdf

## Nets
AVCC_1V2: C291.1 C292.1 FB15.1 U48.60(AVCC12) U48.66(AVCC12)
GND: C73.2 C74.2 C75.2 C76.2 C77.2 C79.2 C80.2 C81.2 C82.2 C83.2 C84.2 C85.2 C86.2 C87.2 C88.2 C89.2 C90.2 C91.2 C92.2 C125.2 C126.2 C133.2 C134.2 C137.2 C256.2 C257.2 C258.2 C259.2 C260.2 C278.2 C279.2 C280.2 C281.2 C282.2 C283.2 C284.2 C285.2 C286.2 C287.2 C288.2 C289.2 C290.2 C291.2 C292.2 C293.2 C294.2 C318.2 C319.2 FB6.1 J5.7(GND2) J5.10(GND3) J5.13(GND4) J5.16(GND5) J5.19(GND6) J5.22(GND7) J5.25(GND8) J5.30(GND9) J5.41(AGND) J5.42(GND1) J6.7(GND2) J6.10(GND3) J6.13(GND4) J6.16(GND5) J6.19(GND6) J6.22(GND7) J6.25(GND8) J6.30(GND9) J6.41(AGND) J6.42(GND1) J7.1 J7.2 J8.4 J8.5 J8.6 J8.13 J8.14 J8.25 J8.26 J9.8 J9.10 J9.13 J9.16 J9.19 J9.22 J9.25 J9.26 J11.3 J11.4 J11.13 J11.14 J11.23 J11.24 J29.2(SHIELD0) J29.5(SHIELD1) J29.8(SHIELD2) J29.11(SHIELD3) J29.17(GND) Q4.2(S) R132.2 R232.2 R233.2 R234.2 R235.2 R236.2 R237.2 R238.2 R239.2 R240.2 R241.2 R242.2 R243.2 R244.2 R245.2 R246.2 R247.2 R299.2 R515.2 R517.2 R518.2 R525.2 R526.1 R527.2 R545.2 R555.2 R567.2 U14.B1(GND_CH1) U14.B2(GND_CH2) U15.B1(GND_CH1) U15.B2(GND_CH2) U16.B1(GND_CH1) U16.B2(GND_CH2) U16.B3(GND_CH3) U17.B1(GND_CH1) U17.B2(GND_CH2) U17.B3(GND_CH3) U18.2(GND) U27.1(GND1) U27.3(GND2) U27.32(CTRL_MODE) U27.33(GND3-PAD) U45.2(GND) U48.43(CGND) U48.55(RSVDL) U48.57(IOGND) U48.63(AGND) U48.70(VDDQ) U48.73(EPAD) U50.2(GND) U51.B1(GND_CH1) U51.B2(GND_CH2) U52.B1(GND_CH1) U52.B2(GND_CH2) U53.2(GND) U54.8(GND) Y1.2(GND) Y2.2(GND) Y7.2(GND) ; also on sheet 1 2 6 7 8 9 10 11 17 18 19 20 21 22 23 24 25
GND_EARTH: C279.1 J29.20(GND0) J29.21(GND3) J29.22(GND1) J29.23(GND2) R526.2 ; also on sheet 6 17 18 19 23 25
VDD_1V2: C278.1 FB14.2 FB15.2 U50.5(OUT)
VDD_1V8: C85.1 C87.1 C137.1 C259.1 R149.1 R153.1 R154.1 R156.1 R157.1 U18.3(VCCA) U18.6(OE) U27.30(VDDD) U45.3(VCCA) U45.6(OE) Y1.4(VCC/Vdd) ; also on sheet 7 9
VDD_3V3: C88.1 C89.1 C91.1 C125.1 C133.1 C134.1 C260.1 C319.1 FB4.1 FB16.2 J11.1 R133.1 R134.1 R135.1 R136.1 R143.1 R145.1 R147.1 R158.1 R159.1 R160.1 R289.1 R521.1 R557.1 U18.7(VCCB) U27.20(VDDIO) U45.7(VCCB) U50.1(IN) U54.16(VCC) Y2.4(VCC/Vdd) ; also on sheet 1 2 7 8 10 11 17 18 19 20 21 25
VDD_5V: C83.1 C84.1 C90.1 C92.1 C281.1 D58.1 D59.1 J9.1 J11.2 R107.1 R530.1 R531.1 U53.7(VCCB) ; also on sheet 1 2 7 17 24
VDD_12V: FB3.2 R117.1 ; also on sheet 6 7
VDD_AUDIO_3V3: C135.1 C136.1 FB4.2 U27.5(VDDA)
VDD_LVD_5V: C73.1 C74.1 C75.1 C76.1 C79.1 C80.1 C256.1 C257.1 C258.1 J5.2(VCC5V) J5.3(VCC5V) J6.2(VCC5V) J6.3(VCC5V) J8.1 J8.2 J8.3 Q3.3(D)
VDD_SOM_3V3: R216.1 R217.1 R218.1 R219.1 R220.1 R221.1 R222.1 R223.1 R224.1 R225.1 R226.1 R227.1 R228.1 R229.1 R230.1 R231.1 ; also on sheet 7 22
AUD_MCASP0_ACLKX: R292.1 U54.3(1B2)
AUD_MCASP0_AFSX: R294.1 U54.6(2B2)
AUD_MCASP0_AXR0: R293.1 U54.10(3B2)
AUD_MCASP0_AXR1: R295.1 U54.13(4B2)
AUD_MIC: C127.1 J14.4(MIC) R297.1
AUDIO_GND: C128.2 C129.2 C130.2 C131.2 C132.2 C135.2 C136.2 FB6.2 R298.2 R569.2 R570.2 U27.7(AGND)
AUDIO_I2C_SCL: U27.29(CTRL_CLK) ; also on sheet 21
AUDIO_I2C_SDA: U27.27(CTRL_DATA) ; also on sheet 21
AUDIO_LOUT_L: C129.1 CT1.2 J14.1(L)
AUDIO_LOUT_R: C128.1 CT2.2 J14.2(R)
AUDIO_MCLK: R288.2 U27.21(SYS_MCLK)
AUDIO_SEL: JP1.1(E1) R557.2 U54.1(S)
BOOTMODE00: R206.2 R216.2 R232.1
BOOTMODE01: R207.2 R217.2 R233.1
BOOTMODE02: R208.2 R221.2 R234.1
BOOTMODE03: R209.2 R241.1 SW2.8(OFF1)
BOOTMODE04: R210.2 R242.1 SW2.7(OFF2)
BOOTMODE05: R211.2 R243.1 SW2.6(OFF3)
BOOTMODE06: R212.2 R244.1 SW2.5(OFF4)
BOOTMODE07: R213.2 R245.1 SW3.8(OFF1)
BOOTMODE08: R197.2 R246.1 SW3.7(OFF2)
BOOTMODE09: R199.2 R247.1 SW3.6(OFF3)
BOOTMODE10: R200.2 R222.2 R235.1
BOOTMODE11: R201.2 R228.2 R236.1
BOOTMODE12: R202.2 R223.2 R237.1
BOOTMODE13: R203.2 R224.2 R238.1
BOOTMODE14: R204.2 R225.2 R239.1
BOOTMODE15: R205.2 R226.2 R240.1
CAM_P1_MCLK: R152.2 Y1.3(OUT/Output)
CAM_RST: R150.2 R154.2 U18.4(A2)
CSI_PWDN: R151.2 R153.2 U18.5(A1)
CVCC_1V2: C282.1 C283.1 C284.1 C285.1 C286.1 C287.1 FB14.1 U48.5(CVCC12) U48.12(CVCC12) U48.26(CVCC12) U48.42(CVCC12) U48.47(CVCC12) U48.53(CVCC12)
FPC_LVDS0_A0N: J6.8(RXIN0-) R118.2
FPC_LVDS0_A0P: J6.9(RXIN0+) R110.2
FPC_LVDS0_A1N: J6.11(RXIN1-) R113.2
FPC_LVDS0_A1P: J6.12(RXIN1+) R115.2
FPC_LVDS0_A2N: J6.14(RXIN2-) R119.2
FPC_LVDS0_A2P: J6.15(RXIN2+) R121.2
FPC_LVDS0_A3N: J6.20(RXIN3-) R128.2
FPC_LVDS0_A3P: J6.21(RXIN3+) R130.2
FPC_LVDS0_CLK0N: J6.17(RXXLK-) R123.2
FPC_LVDS0_CLK0P: J6.18(RXCLK+) R125.2
FPC_LVDS1_A0N: J5.8(RXIN0-) R109.2
FPC_LVDS1_A0P: J5.9(RXIN0+) R111.2
FPC_LVDS1_A1N: J5.11(RXIN1-) R114.2
FPC_LVDS1_A1P: J5.12(RXIN1+) R116.2
FPC_LVDS1_A2N: J5.14(RXIN2-) R120.2
FPC_LVDS1_A2P: J5.15(RXIN2+) R122.2
FPC_LVDS1_A3N: J5.20(RXIN3-) R129.2
FPC_LVDS1_A3P: J5.21(RXIN3+) R131.2
FPC_LVDS1_CLK0N: J5.17(RXXLK-) R124.2
FPC_LVDS1_CLK0P: J5.18(RXCLK+) R126.2
HDMI_CLK+: U48.59(TXC+) U52.C3(CH2_OUT+)
HDMI_CLK-: U48.58(TXC-) U52.C4(CH2_OUT-)
HDMI_CONN_CLKN: J29.12(CLK-) U52.A4(CH2_IN-)
HDMI_CONN_CLKP: J29.10(CLK+) U52.A3(CH2_IN+)
HDMI_CONN_SCL: J29.15(SCL) R522.2 R530.2 U53.8(B1)
HDMI_CONN_SDA: J29.16(SDA) R523.2 R531.2 U53.1(B2)
HDMI_CONN_TX0N: J29.9(D0-) U52.A2(CH1_IN-)
HDMI_CONN_TX0P: J29.7(D0+) U52.A1(CH1_IN+)
HDMI_CONN_TX1N: J29.6(D1-) U51.A4(CH2_IN-)
HDMI_CONN_TX1P: J29.4(D1+) U51.A3(CH2_IN+)
HDMI_CONN_TX2N: J29.3(D2-) U51.A2(CH1_IN-)
HDMI_CONN_TX2P: J29.1(D2+) U51.A1(CH1_IN+)
HDMI_HPD: Q2.2(E) R527.1 U48.54(HPD)
HDMI_I2C_SCL: R529.2 R532.1 U48.49(DSCL)
HDMI_I2C_SDA: R528.2 R533.1 U48.48(DSDA)
HDMI_MCASP0_ACLKX: R161.1 U54.2(1B1)
HDMI_MCASP0_AFSX: R162.1 U54.5(2B1)
HDMI_MCASP0_AXR: R516.1 U54.11(3B1)
HDMI_MCLK: R534.2 U48.38(MCLK)
HDMI_TX0+: U48.62(TX0+) U52.C1(CH1_OUT+)
HDMI_TX0-: U48.61(TX0-) U52.C2(CH1_OUT-)
HDMI_TX1+: U48.65(TX1+) U51.C3(CH2_OUT+)
HDMI_TX1-: U48.64(TX1-) U51.C4(CH2_OUT-)
HDMI_TX2+: U48.68(TX2+) U51.C1(CH1_OUT+)
HDMI_TX2-: U48.67(TX2-) U51.C2(CH1_OUT-)
HP_L: CT1.1 U27.6(HP_L)
HP_R: CT2.1 U27.2(HP_R)
HP_VGND: R298.1 U27.4(HP_VGND)
HPD_DET: J29.19(HOTPLUG) R524.1 R525.1
I2C_SCL_CSI: U45.8(B1) ; also on sheet 21
I2C_SCL_CSI_1V8: J9.5 R156.2 U45.5(A1)
I2C_SDA_CSI: U45.1(B2) ; also on sheet 21
I2C_SDA_CSI_1V8: J9.4 R157.2 U45.4(A2)
I2S_DIN: R293.2 U27.26(I2S_DIN)
I2S_DOUT: R295.2 U27.25(I2S_DOUT)
I2S_LRCLK: R294.2 U27.23(I2S_LRCLK)
I2S_SCLK: R292.2 U27.24(I2S_SCLK)
IOVCC_3V3: C280.1 C288.1 C289.1 C290.1 C293.1 FB16.1 Q2.3(C) R433.1 R514.1 R528.1 R529.1 R535.1 R537.1 U48.3(IOVCC) U48.21(IOVCC) U48.46(IOVCC) U53.3(VCCA) U53.6(OE) Y7.4(VCC/Vdd)
LCD_B0: R163.2 U48.32(VDATA_IN0)
LCD_B1: R164.2 U48.31(VDATA_IN1)
LCD_B2: R165.2 U48.30(VDATA_IN2)
LCD_B3: R166.2 U48.29(VDATA_IN3)
LCD_B4: R167.2 U48.28(VDATA_IN4)
LCD_B5: R168.2 U48.27(VDATA_IN5)
LCD_B6: R169.2 U48.25(VDATA_IN6)
LCD_B7: R170.2 U48.24(VDATA_IN7)
LCD_DE: R194.2 U48.33(DE)
LCD_G0: R171.2 U48.23(VDATA_IN8)
LCD_G1: R172.2 U48.20(VDATA_IN9)
LCD_G2: R173.2 U48.19(VDATA_IN10)
LCD_G3: R174.2 U48.18(VDATA_IN11)
LCD_G4: R175.2 U48.17(VDATA_IN12)
LCD_G5: R176.2 U48.16(VDATA_IN13)
LCD_G6: R177.2 U48.15(VDATA_IN14)
LCD_G7: R178.2 U48.14(VDATA_IN15)
LCD_HSYNC: R196.2 U48.34(HSYNC)
LCD_I2C_SCL: U48.1(CSCL) ; also on sheet 21
LCD_I2C_SDA: U48.2(CSDA) ; also on sheet 21
LCD_PCLK: R198.2 U48.22(IDCK)
LCD_R0: R179.2 U48.13(VDATA_IN16)
LCD_R1: R180.2 U48.11(VDATA_IN17)
LCD_R2: R181.2 U48.10(VDATA_IN18)
LCD_R3: R182.2 U48.9(VDATA_IN19)
LCD_R4: R183.2 U48.8(VDATA_IN20)
LCD_R5: R184.2 U48.7(VDATA_IN21)
LCD_R6: R185.2 U48.6(VDATA_IN22)
LCD_R7: R186.2 U48.4(VDATA_IN23)
LCD_TP_INTn: R190.1 ; also on sheet 21
LCD_TP_INTn_R: R190.2 R433.2 U48.52(INT)
LCD_TP_RESET: R191.1 ; also on sheet 21
LCD_TP_RESET_R: R191.2 R537.2 U48.51(RESETn)
LCD_VSYNC: R195.2 U48.35(VSYNC)
LVDS0_CLKN: J8.15 U16.A4(CH2_IN-)
LVDS0_CLKP: J8.16 U16.A3(CH2_IN+)
LVDS0_D0N: J8.7 U14.A2(CH1_IN-)
LVDS0_D0P: J8.8 U14.A1(CH1_IN+)
LVDS0_D1N: J8.9 U14.A4(CH2_IN-)
LVDS0_D1P: J8.10 U14.A3(CH2_IN+)
LVDS0_D2N: J8.11 U16.A2(CH1_IN-)
LVDS0_D2P: J8.12 U16.A1(CH1_IN+)
LVDS0_D3N: J8.17 U16.A6(CH3_IN-)
LVDS0_D3P: J8.18 U16.A5(CH3_IN+)
LVDS0_I2C_SCL: J6.34(TP_SCK) ; also on sheet 21
LVDS0_I2C_SDA: J6.33(TP_MOSI) ; also on sheet 21
LVDS0_TP_PEN: JP2.2(E2) R143.2 R144.1
LVDS1_CLKN: J8.27 U17.A4(CH2_IN-)
LVDS1_CLKP: J8.28 U17.A3(CH2_IN+)
LVDS1_D0N: J8.19 U15.A2(CH1_IN-)
LVDS1_D0P: J8.20 U15.A1(CH1_IN+)
LVDS1_D1N: J8.21 U15.A4(CH2_IN-)
LVDS1_D1P: J8.22 U15.A3(CH2_IN+)
LVDS1_D2N: J8.23 U17.A2(CH1_IN-)
LVDS1_D2P: J8.24 U17.A1(CH1_IN+)
LVDS1_D3N: J8.29 U17.A6(CH3_IN-)
LVDS1_D3P: J8.30 U17.A5(CH3_IN+)
LVDS1_I2C_SCL: J5.34(TP_SCK) ; also on sheet 21
LVDS1_I2C_SDA: J5.33(TP_MOSI) ; also on sheet 21
LVDS1_TP_PEN: JP3.2(E2) R145.2 R146.1
MCLK_12M: R534.1 Y7.3(OUT/Output)
MIC_BIAS: C130.1 R297.2 U27.16(MIC_BIAS)
MIC_IN: C127.2 U27.15(MIC)
SoC_CSI0_RXCLKN: J9.18 ; also on sheet 22
SoC_CSI0_RXCLKP: J9.17 ; also on sheet 22
SoC_CSI0_RXN0: J9.24 ; also on sheet 22
SoC_CSI0_RXN1: J9.21 ; also on sheet 22
SoC_CSI0_RXN2: J9.15 ; also on sheet 22
SoC_CSI0_RXN3: J9.12 ; also on sheet 22
SoC_CSI0_RXP0: J9.23 ; also on sheet 22
SoC_CSI0_RXP1: J9.20 ; also on sheet 22
SoC_CSI0_RXP2: J9.14 ; also on sheet 22
SoC_CSI0_RXP3: J9.11 ; also on sheet 22
SoC_EXT_REFCLK1: J7.4 R147.2 ; also on sheet 22
SoC_GPMC0_AD0/BOOTMODE00: J11.6 R206.1 ; also on sheet 22
SoC_GPMC0_AD1/BOOTMODE01: J11.8 R207.1 ; also on sheet 22
SoC_GPMC0_AD2/BOOTMODE02: J11.10 R208.1 ; also on sheet 22
SoC_GPMC0_AD3/BOOTMODE03: J11.12 R209.1 ; also on sheet 22
SoC_GPMC0_AD4/BOOTMODE04: J11.16 R210.1 ; also on sheet 22
SoC_GPMC0_AD5/BOOTMODE05: J11.18 R211.1 ; also on sheet 22
SoC_GPMC0_AD6/BOOTMODE06: J11.20 R212.1 ; also on sheet 22
SoC_GPMC0_AD7/BOOTMODE07: J11.22 R213.1 ; also on sheet 22
SoC_GPMC0_ADVn_ALE: J11.17 ; also on sheet 22
SoC_GPMC0_BE0n_CLE: J11.21 ; also on sheet 22
SoC_GPMC0_CLK: J11.5 ; also on sheet 22
SoC_GPMC0_CSn0: J11.7 ; also on sheet 22
SoC_GPMC0_DIR: J11.19 R572.1 ; also on sheet 22
SoC_GPMC0_OEn_REn: J11.11 ; also on sheet 22
SoC_GPMC0_WAIT0: J11.15 R571.1 ; also on sheet 22
SoC_GPMC0_WEn: J11.9 ; also on sheet 22
SoC_LVDS0_A0N: R118.1 U14.C2(CH1_OUT-) ; also on sheet 22
SoC_LVDS0_A0P: R110.1 U14.C1(CH1_OUT+) ; also on sheet 22
SoC_LVDS0_A1N: R113.1 U14.C4(CH2_OUT-) ; also on sheet 22
SoC_LVDS0_A1P: R115.1 U14.C3(CH2_OUT+) ; also on sheet 22
SoC_LVDS0_A2N: R119.1 U16.C2(CH1_OUT-) ; also on sheet 22
SoC_LVDS0_A2P: R121.1 U16.C1(CH1_OUT+) ; also on sheet 22
SoC_LVDS0_A3N: R128.1 U16.C6(CH3_OUT-) ; also on sheet 22
SoC_LVDS0_A3P: R130.1 U16.C5(CH3_OUT+) ; also on sheet 22
SoC_LVDS0_CLK0N: R123.1 U16.C4(CH2_OUT-) ; also on sheet 22
SoC_LVDS0_CLK0P: R125.1 U16.C3(CH2_OUT+) ; also on sheet 22
SoC_LVDS1_A0N: R109.1 U15.C2(CH1_OUT-) ; also on sheet 22
SoC_LVDS1_A0P: R111.1 U15.C1(CH1_OUT+) ; also on sheet 22
SoC_LVDS1_A1N: R114.1 U15.C4(CH2_OUT-) ; also on sheet 22
SoC_LVDS1_A1P: R116.1 U15.C3(CH2_OUT+) ; also on sheet 22
SoC_LVDS1_A2N: R120.1 U17.C2(CH1_OUT-) ; also on sheet 22
SoC_LVDS1_A2P: R122.1 U17.C1(CH1_OUT+) ; also on sheet 22
SoC_LVDS1_A3N: R129.1 U17.C6(CH3_OUT-) ; also on sheet 22
SoC_LVDS1_A3P: R131.1 U17.C5(CH3_OUT+) ; also on sheet 22
SoC_LVDS1_CLK0N: R124.1 U17.C4(CH2_OUT-) ; also on sheet 22
SoC_LVDS1_CLK0P: R126.1 U17.C3(CH2_OUT+) ; also on sheet 22
SoC_MCASP0_ACLKX: U54.4(1A) ; also on sheet 22
SoC_MCASP0_AFSX: U54.7(2A) ; also on sheet 22
SoC_MCASP0_AXR0: U54.9(3A) ; also on sheet 22
SoC_MCASP0_AXR1: U54.12(4A) ; also on sheet 22
SoC_MCU_SPI0_CLK: R158.2 U18.8(B1) ; also on sheet 22
SoC_MCU_SPI0_CS0: R159.2 U18.1(B2) ; also on sheet 22
SoC_MCU_SPI0_D0: R148.2 R160.2 ; also on sheet 22
SoC_MCU_SPI0_D1: R127.2 ; also on sheet 22
SoC_SPI0_CLK: J7.3 ; also on sheet 22
SoC_SPI0_CS0: R136.2 R138.1 ; also on sheet 22
SoC_SPI0_CS1: R135.2 R137.1 ; also on sheet 22
SoC_SPI0_D0: R133.2 R139.1 ; also on sheet 22
SoC_SPI0_D1: R134.2 R140.1 ; also on sheet 22
SoC_VOUT0_DATA0: R163.1 ; also on sheet 22
SoC_VOUT0_DATA1: R164.1 ; also on sheet 22
SoC_VOUT0_DATA2: R165.1 ; also on sheet 22
SoC_VOUT0_DATA3: R166.1 ; also on sheet 22
SoC_VOUT0_DATA4: R167.1 ; also on sheet 22
SoC_VOUT0_DATA5: R168.1 ; also on sheet 22
SoC_VOUT0_DATA6: R169.1 ; also on sheet 22
SoC_VOUT0_DATA7: R170.1 ; also on sheet 22
SoC_VOUT0_DATA8: R171.1 ; also on sheet 22
SoC_VOUT0_DATA9: R172.1 ; also on sheet 22
SoC_VOUT0_DATA10: R173.1 ; also on sheet 22
SoC_VOUT0_DATA11: R174.1 ; also on sheet 22
SoC_VOUT0_DATA12: R175.1 ; also on sheet 22
SoC_VOUT0_DATA13: R176.1 ; also on sheet 22
SoC_VOUT0_DATA14: R177.1 ; also on sheet 22
SoC_VOUT0_DATA15: R178.1 ; also on sheet 22
SoC_VOUT0_DATA16/BOOTMODE08: R179.1 R197.1 ; also on sheet 22
SoC_VOUT0_DATA17/BOOTMODE09: R180.1 R199.1 ; also on sheet 22
SoC_VOUT0_DATA18/BOOTMODE10: R181.1 R200.1 ; also on sheet 22
SoC_VOUT0_DATA19/BOOTMODE11: R182.1 R201.1 ; also on sheet 22
SoC_VOUT0_DATA20/BOOTMODE12: R183.1 R202.1 ; also on sheet 22
SoC_VOUT0_DATA21/BOOTMODE13: R184.1 R203.1 ; also on sheet 22
SoC_VOUT0_DATA22/BOOTMODE14: R185.1 R204.1 ; also on sheet 22
SoC_VOUT0_DATA23/BOOTMODE15: R186.1 R205.1 ; also on sheet 22
SoC_VOUT0_DE: R194.1 ; also on sheet 22
SoC_VOUT0_HSYNC: R196.1 ; also on sheet 22
SoC_VOUT0_PCLK: R198.1 ; also on sheet 22
SoC_VOUT0_VSYNC: R195.1 ; also on sheet 22
N19629412: C321.1 U27.14(LINEIN_L)
N19629418: C322.1 U27.13(LINEIN_R)
N19629536: J14.3(AUD_GND) R570.1
N19629600: C131.1 U27.10(VAG)
N19629602: C132.1 U27.18(CPFLT)
N19629628: R299.1 U27.31(CTRL_ADR0_CS)
N20386876: J9.9 R152.1
N20386882: J9.6 R150.1
N20386885: J9.7 R151.1
N20386918: J9.2 R148.1
N20390587: Q4.1(G) R127.1 R132.1
N20390701: Q4.3(D) R108.2 R112.2
N20390757: C77.1 C78.1 Q3.2(S) R107.2 R108.1 R117.2
N20390883: C78.2 Q3.1(G) R112.1
N20656670: R288.1 Y2.3(OUT/Output)
N21450803: R231.2 SW3.2(ON2)
N21450805: R227.2 SW3.3(ON3)
N21838021: C81.1 C82.1 FB3.1 J7.5 J7.6
N22230603: C126.1 R289.2 Y2.1(EN/Vcont/NC)
N22232243: C86.1 R149.2 Y1.1(EN/Vcont/NC)
N22348627: J6.27(BL_CTR) R137.2
N22348634: J6.28(TP_CS) R139.2
N22348696: J6.36(TP_PEN) R144.2
N22355541: J5.27(BL_CTR) R138.2
N22355547: J5.28(TP_CS) R140.2
N22355619: J5.36(TP_PEN) R146.2
N22513317: R218.2 SW2.2(ON2)
N22513319: R219.2 SW2.3(ON3)
N22513321: R220.2 SW2.4(ON4)
N22513323: R230.2 SW3.1(ON1)
N22515068: R229.2 SW2.1(ON1)
N22709458: R514.2 U48.72(CI2CA)
N22710105: R515.1 U48.36(SPDIF)
N22710530: R516.2 U48.41(SD0)
N22712478: R517.1 U48.69(IO_SEL)
N22712757: R518.1 U48.56(EXT_SWING)
N22714174: R521.2 R545.1 U50.3(EN)
N22724008: Q2.1(B) R524.2
N22724271: R532.2 U53.5(A1)
N22724282: R533.2 U53.4(A2)
N22746676: C294.1 R535.2 Y7.1(EN/Vcont/NC)
N22751077: D58.2 J29.18(+5V)
N22751165: D59.2 R522.1 R523.1
N22843605: C318.1 U50.4(BP/FB)
N22857632: R161.2 U48.45(SCK)
N22857662: R162.2 U48.44(WS)
N22865159: R555.1 U54.15(nOE)
N22982457: JP1.2(E2) R567.1
N22991878: C321.2 C322.2 R569.1
N23013826: JP2.1(E1) R571.2
N23013829: JP3.1(E1) R572.2

Not connected (* = marked no-connect by the designer): J5 1(NC1) 4(NC2) 5(NC3) 6(NC4) 23(NC5) 24(NC6) 26(NC7) 29(NC8) 31(NC9) 32(NC0) 35(NC10) 37(NC11) 38(NC12) 39(NC13) 40(NC14); J6 1(NC1) 4(NC2) 5(NC3) 6(NC4) 23(NC5) 24(NC6) 26(NC7) 29(NC8) 31(NC9) 32(NC0) 35(NC10) 37(NC11) 38(NC12) 39(NC13) 40(NC14); J9 3; J11 25 26 27 28 29 30; J14 5(NC5) 6(NC6) 7(shell1) 8(shell2); J29 13(CEC)* 14(NC)*; SW3 4(ON4) 5(OFF4); U27 8(NC1)* 9(NC2)* 11(LINEOUT_R)* 12(LINEOUT_L)* 17(NC3)* 19(NC4)* 22(NC5)* 28(NC6)*; U48 37(SD3)* 39(SD2)* 40(SD1)* 50(CEC_D) 71(CEC_A); U54 14(4B1)*

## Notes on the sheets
sheet 12
- LVDS Dual Channel
- LVDS Single Channel（duplicate）
- MCU_GPIO0_4
- H :Power on
  L :Power off
- EHRPWM0_B
- EHRPWM0_A
- GPIO1_18
- GPIO1_19
- BKL_EN
- GPIO1_30
- PWM
- BACK LIGHT
- EHRPWM1_A
- LVDS Dual Channel
- ODD PIXELS
- EVEN PIXELS
- Note that the OLDI TX0 transmits the odd set of pixels while the OLDI TX1 transmits the even set.
  This is a fixed configuration in the IP integration and is not  changeable.
sheet 13
- Camera Interface
- 1.8V/3.3V
- MCU_GPIO0_3
- MCU_GPIO0_2
- MCU_GPIO0_0
sheet 14
- RGB TO HDMI
- 22R series resistor placed close to SOM connector.
- 100E
- 100E
- 100E
- 100E
- R161、R162 placed close to SOM connector.
- NOTE: 1K resistors placed on cross point.
- 8 bit GPMC
- GPMC IO Switch
- CPU
- GPMC
- J11
- JP2 & JP3 Connect : LVDS
  JP2 & JP3 Disconnect : GPMC
- 1K
- BOOTMODE
  PIN[7:0]
- SW2~SW3
- CPU
- HDMI
- U48
- 1K
- BOOTMODE
  PIN[15:8]
- J11
- NOTE: Resistors are used to isolate the BOOTMODE control logic after the value is latched
sheet 15
- BOOT MODE SWITCHES
- Silk: BMODE 0-7
- SWITCH ON  =  LOGIC 1
  SWITCH OFF =  LOGIC 0
sheet 16
- Audio Codec
- C131,C132 should be placed close to U27 pins.
- R570 Closed to audio connector
- AUDIO IO Expander
- AUDIO_SEL=High,A=B2
  AUDIO_SEL=Low,A=B1
- P2P Replace：RUN-IC RS2233YTSS16
